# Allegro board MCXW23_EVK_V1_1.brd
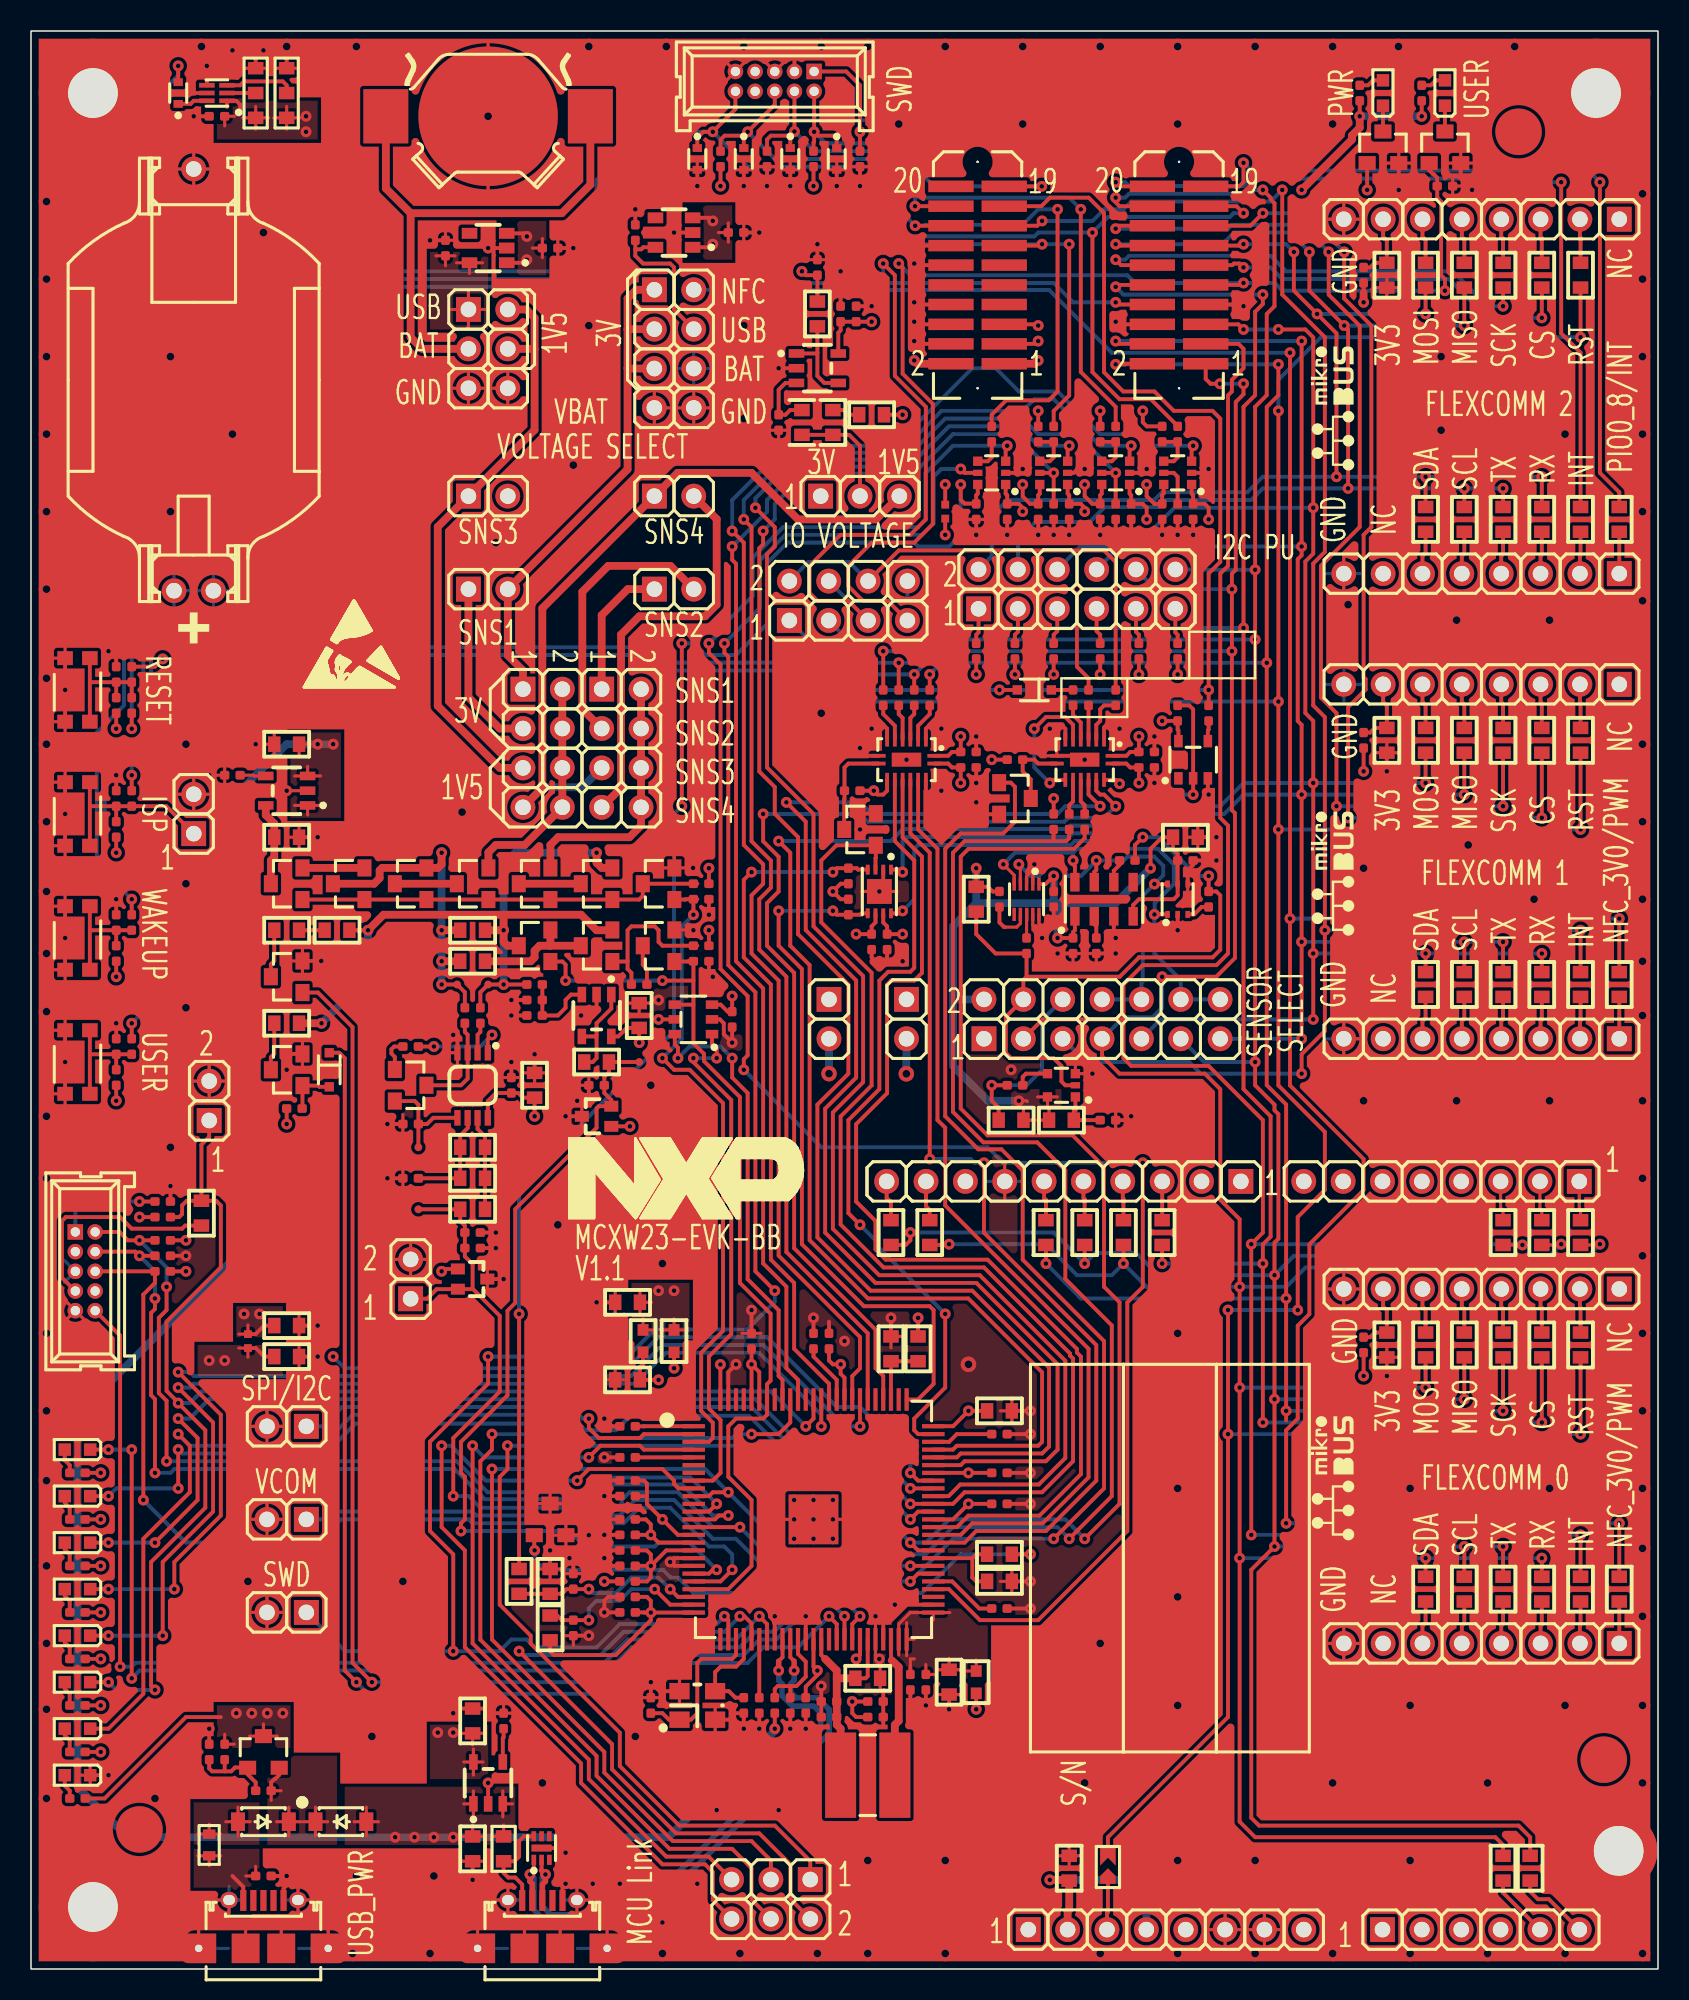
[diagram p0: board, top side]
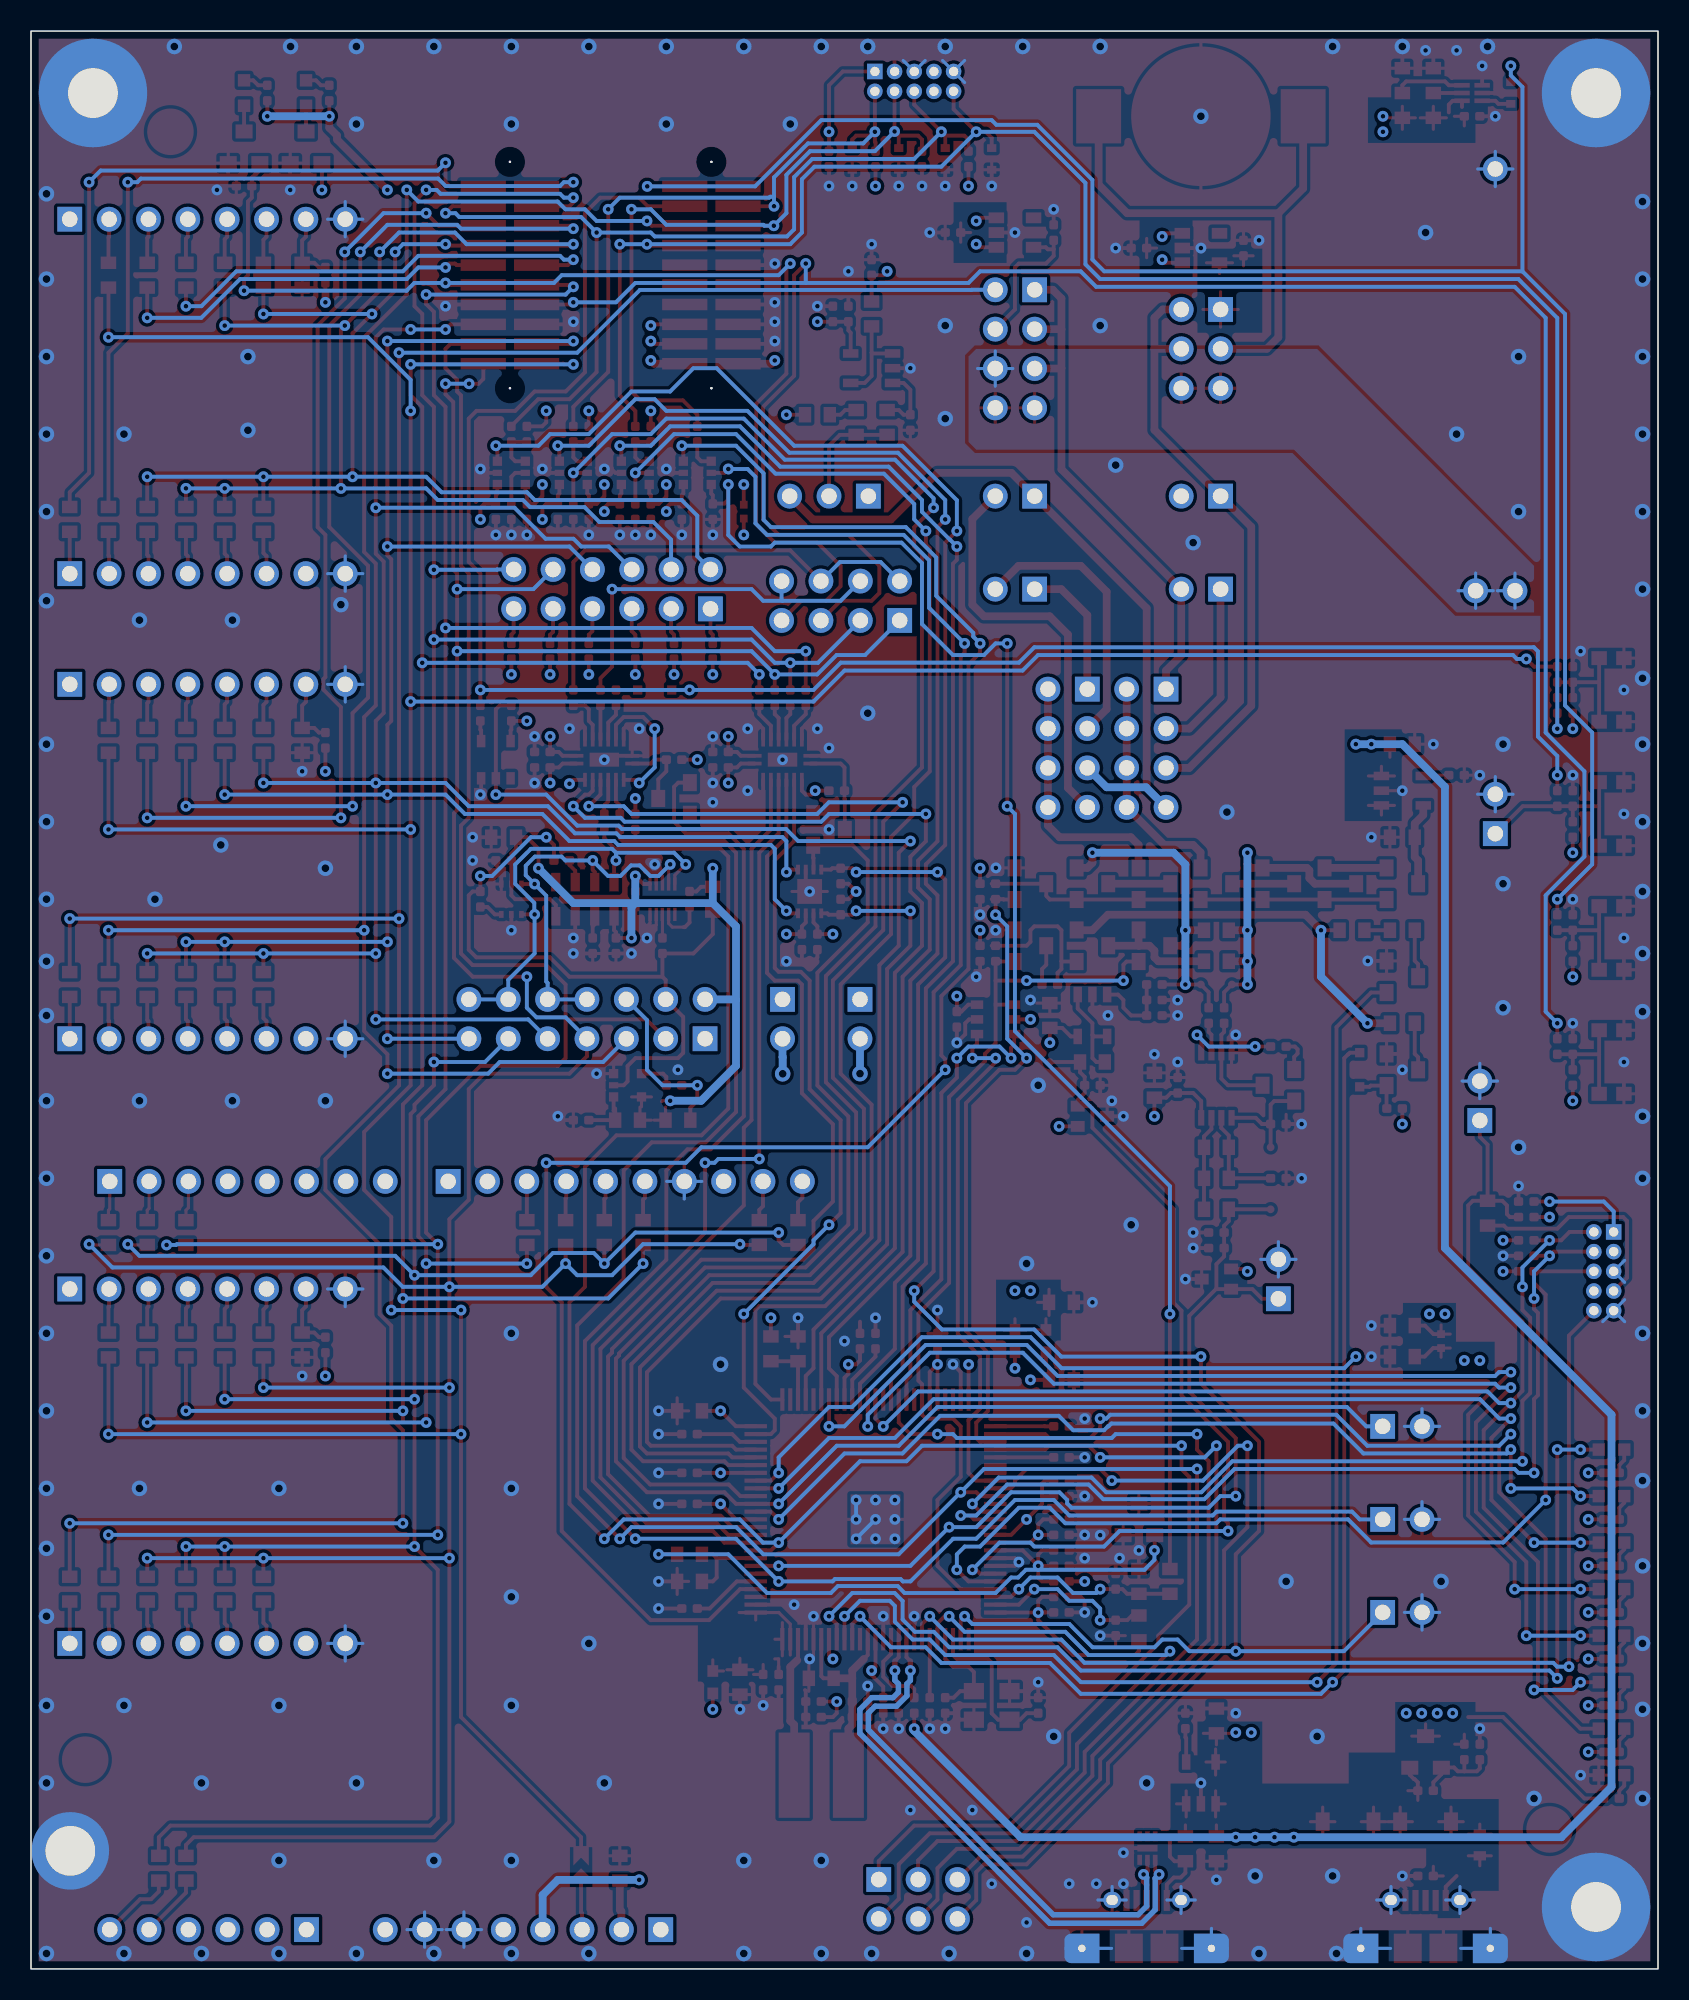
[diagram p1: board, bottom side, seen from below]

Outline 105 x 125 mm; copper layers: TOP, IN1, IN2, BOTTOM. Coordinates in mm from the lower left corner of the outline.
Outline path: rectangle 0,0 105,125

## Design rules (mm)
constraint set DEFAULT: 
net group USB: nets USB_DM USB_DP

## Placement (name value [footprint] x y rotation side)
BAT2  BATTERY_HOLDER  [RENATA-HU2032-LF]  10.5 102.5 90 top
BAT3  Keystone_3030  [KEYSTONE-3030]  29.5 119.5 0 top
BD1  470 Ohm @ 100MHz  [0603-R]  30.5 7.75 90 top
C1  1uF  [CC0402_25]  33.5 111 0 top
C2  1uF  [CC0402_25]  26.75 111 90 top
C3  100nF  [CC0402_25]  12 119.5 180 top
C4  1uF  [CC0402_25]  45.5 112 0 top
C5  1uF  [CC0402_25]  39 112 90 top
C6  100nF  [CC0402_25]  52.25 106.75 270 top
C7  1uF  [CC0402_25]  53.25 106.75 90 top
C8  10nF  [CC0402_25]  5.5 83.5 90 top
C9  10nF  [CC0402_25]  5.5 75.5 90 top
C10  10nF  [CC0402_25]  5.5 67.5 90 top
C11  10nF  [CC0402_25]  5.5 59.5 90 top
C12  100nF  [CC0402_25]  53.5 116.75 270 top
C13  100nF  [CC0402_25]  69.5 54.75 180 top
C14  100nF  [CC0402_25]  66 69 90 top
C15  100nF  [CC0402_25]  67.25 66 90 top
C16  100nF  [CC0402_25]  68.75 66 90 top
C17  100nF  [CC0402_25]  74.5 71.5 180 top
C18  10uF  [CC0603_OV]  87.5 40.25 270 top
C19  10uF  [CC0603_OV]  87.5 79.25 270 top
C20  10uF  [CC0603_OV]  87.5 109.25 270 top
C21  4.7UF  [CC0603_OV]  67 6.5 90 top
C22  100nF  [CC0402_25]  35 25 90 top
C23  100nF  [CC0402_25]  8.5 49.5 0 top
C24  10uF  [CC0603_OV]  62.5 36 0 top
C25  4.7UF  [CC0603_OV]  38.5 38 180 top
C26  100nF  [CC0402_25]  38.5 31.5 180 top
C27  100nF  [CC0402_25]  38.5 23 180 top
C28  100nF  [CC0402_25]  50 17 270 top
C29  100nF  [CC0402_25]  62.5 30 0 top
C30  100nF  [CC0402_25]  46.5 40.5 90 top
C31  10nF  [CC0402_25]  38.5 30.5 180 top
C32  10nF  [CC0402_25]  38.5 24 180 top
C33  10nF  [CC0402_25]  62.5 32 0 top
C34  10nF  [CC0402_25]  51.5 40.5 90 top
C35  47pF  [CC0402_25]  56.75 18.5 270 top
C36  100nF  [CC0402_25]  57.75 18.5 270 top
C37  22uF  [CC0603_OV]  59.25 18.5 270 top
C38  10uF  [CC0603_OV]  38.5 43 180 top
C39  100nF  [CC0402_25]  38.5 28 180 top
C40  47pF  [CC0402_25]  38.5 29 180 top
C41  47pF  [CC0402_25]  51.5 16.25 180 top
C42  100nF  [CC0402_25]  51.5 17.25 180 top
C43  22uF  [CC0603_OV]  54 18.75 0 top
C44  100nF  [CC0402_25]  38.5 27 180 top
C45  10nF  [CC0402_25]  38.5 26 180 top
C46  12PF  [CC0402_25]  46 17 270 top
C47  12PF  [CC0402_25]  40 17 90 top
C48  100nF  [CC0402_25]  54.5 17.25 0 top
C49  100nF  [CC0402_25]  54.5 16.25 0 top
C50  1uF  [CC0603_OV]  28.5 7.75 90 top
C51  4.7uF  [CC0603_OV]  28.5 16 90 top
C52  100nF  [CC0402_25]  30.5 16 90 top
C53  2.2UF  [CC0402_25]  15 6 0 top
C54  22uF  [CC0603_OV]  16.5 41.5 0 top
C55  22uF  [CC0603_OV]  16.5 39.5 0 top
C60  100nF  [CC0402_25]  45.25 61.25 270 top
C61  10uF  [CC0603_OV]  39.25 61.5 90 top
C62  1nF  [CC0402_25]  32.5 61.5 180 top
C63  10pF  [CC0402_25]  36.5 57 180 top
C64  10uF  [CC0603_OV]  32.5 57 90 top
C65  100nF  [CC0402_25]  31 57 90 top
C66  10pF  [CC0402_25]  28.5 46.5 0 top
C67  100PF  [CC0603_OV]  28.5 51 0 top
C68  100nF  [CC0402_25]  72 78.5 0 top
C69  100nF  [CC0402_25]  72 77.5 0 top
C70  100nF  [CC0402_25]  60.5 77.5 0 top
C71  100nF  [CC0402_25]  60.5 78.5 0 top
C72  100nF  [CC0402_25]  54.25 66.25 270 top
C73  100nF  [CC0402_25]  55.25 66.25 270 top
C74  100nF  [CC0402_25]  69 94 270 top
C75  100nF  [CC0402_25]  71 94 270 top
C76  100nF  [CC0402_25]  63 94 270 top
C77  100nF  [CC0402_25]  61 94 270 top
C78  100nF  [CC0402_25]  65 94 270 top
C79  100nF  [CC0402_25]  67 94 270 top
C80  100nF  [CC0402_25]  75 94 270 top
C81  100nF  [CC0402_25]  73 94 270 top
C83  100nF  [CC0402_25]  12.5 14 270 top
C87  4.7UF  [CC0603_OV]  74.5 73 0 top
C88  4.7uF  [CC0603_OV]  16.5 73 0 top
C89  100nF  [CC0402_25]  13 77 180 top
C90  1uF  [CC0603_OV]  16.5 79 0 top
D1  RB751S40T1G  [SOD523]  9.5 121 90 top
D2  GREEN  [KINGBRIGHT-KP1608]  91.25 121 270 top
D3  GREEN  [KINGBRIGHT-KP1608]  87.25 121 270 top
D4  PESD3V3S1UB  [SOD523]  43 116.75 270 top
D5  PESD3V3S1UB  [SOD523]  46 116.75 270 top
D6  PESD3V3S1UB  [SOD523]  49 116.75 270 top
D7  PESD3V3S1UB  [SOD523]  52 116.75 270 top
D8  GREEN  [KINGBRIGHT-KP1608]  3 27.5 0 top
D9  GREEN  [KINGBRIGHT-KP1608]  3 15.5 0 top
D10  RED  [KINGBRIGHT-KP1608]  3 18.5 0 top
D11  GREEN  [KINGBRIGHT-KP1608]  3 24.5 0 top
D12  GREEN  [KINGBRIGHT-KP1608]  3 21.5 0 top
D13  GREEN  [KINGBRIGHT-KP1608]  3 33.5 0 top
D14  GREEN  [KINGBRIGHT-KP1608]  3 30.5 0 top
D16  BLUE  [KINGBRIGHT-KP1608]  3 12.5 0 top
D17  PMEG6002EJ,115  [SOD323F-R]  64.75 82.5 180 top
D18  PMEG4010EGWX  [SOD123]  20 9.5 0 top
D19  PMEG4010EGWX  [SOD123]  15 9.5 180 top
D20  PMEG6002EJ,115  [SOD323F-R]  19.25 58 270 top
FIX1  3.2mm  [FM32_CU70]  4 4 0 top
FIX2  3.2mm  [FM32_CU70]  4 121 0 top
FIX3  3.2mm  [FM32_CU70]  101 121 0 top
FIX4  3.2mm  [FM32_CU70]  102.46 7.62 0 top
J1  CONN_HDR_4X2  [HE14-2X4PTS-MD]  33.02 78.74 270 top
J2  CONN_HDR_4X2  [HE14-2X4PTS-MD]  38.1 78.74 270 top
J3  CONN_HDR_3X1  [HE14-3PTS-MD]  53.5 95 0 top
J4  CONN_HDR_4X2  [HE14-2X4PTS-MD]  41.5 104.5 270 top
J5  CONN_HDR_3X2  [HE14-2X3PTS-MD]  29.5 104.5 270 top
J6  CONN_HDR_1X2  [HE14-2X1PTS-MD]  29.5 95 270 top
J7  CONN_HDR_1X2  [HE14-2X1PTS-MD]  41.5 95 270 top
J8  TFC-110-02-L-D-A  [SAMTEC-TFC-110-02-L-D-A]  61.09 109.26 0 top
J9  CONN_HDR_1X2  [HE14-2X1PTS-MD]  41.5 89 270 top
J10  CONN_HDR_1X2  [HE14-2X1PTS-MD]  29.5 89 270 top
J11  SHF-105-01-L-D-TH  [SAMTEC-SHF-105-01-L-D-TH]  48 121.75 180 top
J12  TFC-110-02-L-D-A  [SAMTEC-TFC-110-02-L-D-A]  74.09 109.26 0 top
J13  CONN_HDR_7X2  [HE14-2X7PTS-MD]  69.12 61.27 0 top
J14  CON SKT 8  [HE14-8PTS-MD]  93.61 43.86 180 top
J15  CON SKT 8  [HE14-8PTS-MD]  93.61 21 180 top
J16  CONN_HDR_2X1  [HE14-2X1PTS-MD]  56.5 61.27 180 top
J17  CON SKT 8  [HE14-8PTS-MD]  93.61 60 180 top
J18  CON SKT 8  [HE14-8PTS-MD]  93.61 82.86 180 top
J19  CONN_HDR_6X2  [HE14-2X6PTS-MD]  67.5 89 0 top
J20  CON SKT 8  [HE14-8PTS-MD]  93.61 112.86 180 top
J21  CON SKT 8  [HE14-8PTS-MD]  93.61 90 180 top
J22  CONN_HDR_2X1  [HE14-2X1PTS-MD]  51.5 61.27 180 top
J23  CON SKT 8  [HE14-8PTS-MD]  73.25 2.54 0 top
J24  Con_10x1  [HE14-10PTS-MD]  66.65 50.8 180 top
J25  Con_6x1  [HE14-6PTS-MD]  93.57 2.54 0 top
J26  CON SKT 8  [HE14-8PTS-MD]  91.03 50.8 180 top
J27  CONN_HDR_3X2  [HE14-2X3PTS-MD]  47.75 4.5 180 top
J28  CONN_HDR_2X1  [HE14-2X1PTS-MD]  16.5 35 90 top
J29  CONN_HDR_2X1  [HE14-2X1PTS-MD]  16.5 29 90 top
J30  CONN_HDR_2X1  [HE14-2X1PTS-MD]  16.5 23 90 top
J31  SHF-105-01-L-D-TH  [SAMTEC-SHF-105-01-L-D-TH]  3.5 45 270 top
J32  CONN_HDR_2X1  [HE14-2X1PTS-MD]  11.5 56 0 top
J33  USB Micro-B  [WE-629_105_150_921]  33 0 0 top
J34  USB Micro-B  [WE-629_105_150_921]  15 0 0 top
J35  CONN_HDR_2X1  [HE14-2X1PTS-MD]  24.5 44.5 0 top
J36  CONN_HDR_4X2  [HE14-2X4PTS-MD]  52.75 88.25 0 top
J37  CONN_HDR_2X1  [HE14-2X1PTS-MD]  10.5 74.5 0 top
JP37  Solderjumper  [PST-SD2]  69.5 6.5 0 top
L1  600OHM  [WE-CBF_0603-HS]  39.5 40.5 270 top
L2  600OHM  [WE-CBF_0603-HS]  61 18.5 90 top
L3  600OHM  [WE-CBF_0603-HS]  41.5 40.5 270 top
L4  4.7uH  [MURATA-LQH5BP]  54 12.5 180 top
L5  330 OHM  [TDK-MPZ1608]  11.5 8 90 top
L6  1K  [MURATA-BLM15]  14 40.5 270 top
L7  1K  [MURATA-BLM15]  59 94 270 top
NOREF  -  []  85 67 90 top
NOREF#2  -  []  -90 -64 0 top
NOREF#3  -  []  0 0 90 top
NOREF#4  -  [unnamed#2]  96 118.5 0 top
NOREF#5  -  []  -7 -7 0 top
NOREF#6  -  []  87 -10 0 top
NOREF#7  -  []  85 97 90 top
NOREF#8  -  []  105 0 90 top
NOREF#9  -  [unnamed#2]  7 9 0 top
NOREF#10  -  []  -7 132 0 top
NOREF#11  -  []  112 132 0 top
NOREF#12  -  []  85 28 90 top
NOREF#13  -  []  -87 -61 0 top
NOREF#14  -  []  0 125 0 top
NOREF#15  -  [unnamed#2]  101.5 13.5 0 top
NOREF#16  -  []  0 0 0 top
NOREF#17  -  []  202 -61 180 bottom
Q1  PMV30UN2R  [SOT23_GSD]  91.25 117.5 0 top
Q2  PMV30UN2R  [SOT23_GSD]  87.25 117.5 0 top
Q7  PMV30UN2R  [SOT23_GSD]  36.5 66 90 top
Q8  PMV30UN2R  [SOT23_GSD]  40.5 66 90 top
Q9  PMV30UN2R  [SOT23_GSD]  24.5 57 270 top
Q10  BSS138P  [SOT23_GSD]  63.5 75.5 270 top
Q11  BSS138P  [SOT23_GSD]  53.5 73.5 90 top
Q12  PMV65XP  [SOT23_GSD]  15 14 0 top
Q14  PMV27UPE  [SOT23_GSD]  32.5 66 90 top
Q16  PMV30UN2R  [SOT23_GSD]  16.5 58 90 top
Q17  PMV30UN2R  [SOT23_GSD]  16.5 64 90 top
Q20  Si2333DS  [SOT23_GSD]  16.5 70 90 top
Q21  PMV30UN2R  [SOT23_GSD]  40.5 70 90 top
Q22  Si2333DS  [SOT23_GSD]  20.5 70 90 top
Q24  PMV30UN2R  [SOT23_GSD]  28.5 70 90 top
Q25  PMV30UN2R  [SOT23_GSD]  24.5 70 90 top
Q26  PMV30UN2R  [SOT23_GSD]  32.5 70 90 top
Q27  PMV30UN2R  [SOT23_GSD]  36.5 70 90 top
R1  0R  [R603-X2]  14.5 121 90 top
R2  0R  [R603-X2]  16.5 121 90 top
R3  510  [RC0402_25]  89.75 121 90 top
R5  100K  [RC0402_25]  5.5 81.5 90 top
R6  100K  [RC0402_25]  5.5 73.5 90 top
R7  100K  [RC0402_25]  5.5 65.5 90 top
R8  100K  [RC0402_25]  5.5 57.5 90 top
R9  510  [RC0402_25]  85.75 121 90 top
R10  1K  [RC0402_25]  6.5 81.5 270 top
R11  1K  [RC0402_25]  6.5 83.5 90 top
R12  0R  [RC0603_OV]  51.75 99.75 90 top
R13  0R  [RC0603_OV]  54.25 100.25 0 top
R14  100K  [RC0402_25]  91.25 115 0 top
R15  1K  [RC0402_25]  6.5 75.5 90 top
R16  1K  [RC0402_25]  6.5 67.5 90 top
R17  0R  [RC0603_OV]  49.75 99.75 90 top
R18  100K  [RC0402_25]  50.75 109.75 90 top
R19  0R  [RC0603_OV]  50.75 106.75 90 top
R20  100K  [RC0402_25]  48.25 99.75 90 top
R21  1K  [RC0402_25]  6.5 59.5 90 top
R22  100K  [RC0402_25]  44.5 116.75 270 top
R23  100K  [RC0402_25]  50.5 116.75 270 top
R24  100K  [RC0402_25]  47.5 116.75 90 top
R25  10K  [RC0603_OV]  66.5 54.75 0 top
R26  10K  [RC0603_OV]  61 69 270 top
R27  1K  [RC0402_25]  63.5 57 0 top
R29  0R  [RC0402_25]  86 40.25 90 top
R30  0R  [RC0402_25]  86 79.25 90 top
R31  2.2K  [RC0402_25]  61 85 90 top
R32  2.2K  [RC0402_25]  66 85 90 top
R33  2.2K  [RC0402_25]  63.5 85 90 top
R34  2.2K  [RC0402_25]  71.5 85 90 top
R35  2.2K  [RC0402_25]  69 85 90 top
R36  2.2K  [RC0402_25]  74 85 90 top
R37  0R  [RC0402_25]  86 109.25 90 top
R38  200K  [RC0603_OV]  33.5 22 90 top
R39  100K  [RC0402_25]  35 22 270 top
R40  0  [RC0603_OV]  62.5 26.75 0 top
R41  0R  [RC0603_OV]  62.5 25 180 top
R42  2.0K  [RC0603_OV]  31.5 25 270 top
R43  2.0K  [RC0603_OV]  33.5 25 90 top
R44  510  [RC0402_25]  3 26 180 top
R45  510  [RC0402_25]  3 14 180 top
R46  1K  [RC0402_25]  62.5 23.25 0 top
R47  1K  [RC0402_25]  50.5 40.5 90 top
R48  1K  [RC0402_25]  62.5 34.5 0 top
R49  1K  [RC0402_25]  38.5 35 180 top
R50  1K  [RC0402_25]  47 17 270 top
R51  1K  [RC0402_25]  38.5 33 180 top
R52  100K  [RC0402_25]  8.5 45 180 top
R53  100K  [RC0402_25]  8.5 47 180 top
R54  510  [RC0402_25]  3 17 180 top
R55  100K  [RC0402_25]  8.5 48.5 0 top
R56  510  [RC0402_25]  3 23 180 top
R57  0  [RC0603_OV]  11 48.75 270 top
R58  510  [RC0402_25]  3 20 180 top
R59  510  [RC0402_25]  3 32 180 top
R60  100K  [RC0402_25]  8.5 46 0 top
R61  510  [RC0402_25]  3 29 180 top
R62  1K  [RC0402_25]  38.5 25 0 top
R63  10K  [RC0402_25]  48 17 90 top
R64  20K  [RC0402_25]  49 17 270 top
R65  510  [RC0402_25]  3 11 180 top
R66  10K  [RC0402_25]  43.25 70 0 top
R67  6.65K  [RC0603_OV]  16.5 61 0 top
R71  66.5  [RC0603_OV]  16.5 67 0 top
R72  330K  [RC0402_25]  43.25 66 0 top
R73  2  [RC0603_OV]  28.5 65 0 top
R74  10K  [RC0402_25]  43.25 65 0 top
R75  330K  [RC0402_25]  32.5 63.5 0 top
R76  0  [RC0603_OV]  36.5 58.5 0 top
R77  330K  [RC0402_25]  32.5 62.5 0 top
R78  100R  [RC0402_25]  29 61.5 270 top
R79  100R  [RC0402_25]  28 61.5 270 top
R80  49.9  [RC0402_25]  24.5 59.5 180 top
R81  1K  [RC0402_25]  24.5 51 0 top
R82  0  [RC0603_OV]  28.5 49 180 top
R83  1K  [RC0402_25]  24.5 54.5 180 top
R84  1K  [RC0402_25]  28.5 47.5 180 top
R85  2K  [RC0603_OV]  28.5 53 0 top
R87  100  [RC0402_25]  70 82 90 top
R88  10K  [RC0402_25]  66 74 270 top
R89  100  [RC0402_25]  68.25 82 90 top
R90  100  [RC0402_25]  67.25 82 90 top
R91  100  [RC0402_25]  68 74 90 top
R92  100  [RC0402_25]  67 74 90 top
R93  10K  [RC0402_25]  63.5 78 0 top
R94  100  [RC0402_25]  58 82 90 top
R95  100  [RC0402_25]  56 82 90 top
R96  100  [RC0402_25]  57 82 90 top
R97  100  [RC0402_25]  55 82 90 top
R98  10K  [RC0402_25]  53 76 180 top
R99  10K  [RC0402_25]  74 81 90 top
R100  10  [RC0402_25]  76 81 90 top
R101  2.2K  [RC0402_25]  52.75 68.5 270 top
R102  2.2K  [RC0402_25]  52.75 70.5 90 top
R104  100K  [RC0402_25]  69 99 270 top
R105  10  [RC0402_25]  70 99 90 top
R106  2.2K  [RC0402_25]  70 94 270 top
R108  100K  [RC0402_25]  65 99 270 top
R109  10  [RC0402_25]  62 99 90 top
R110  10  [RC0402_25]  66 99 90 top
R111  2.2K  [RC0402_25]  66 94 270 top
R112  100K  [RC0402_25]  73 99 270 top
R114  10  [RC0402_25]  74 99 90 top
R115  2.2K  [RC0402_25]  74 94 270 top
R116  0R  [RC0603_OV]  55.5 47.5 270 top
R118  0R  [RC0603_OV]  58 47.5 270 top
R119  0R  [RC0603_OV]  65.5 47.5 270 top
R120  0R  [RC0603_OV]  68 47.5 270 top
R121  0R  [RC0603_OV]  70.5 47.5 270 top
R122  0R  [RC0603_OV]  73 47.5 270 top
R123  0R  [RC0603_OV]  97.5 47.5 270 top
R124  0R  [RC0603_OV]  100 47.5 270 top
R125  0R  [RC0603_OV]  95 47.5 270 top
R126  0R  [RC0603_OV]  95 6.5 270 top
R127  0R  [RC0603_OV]  96.75 6.5 270 top
R128  0R  [RC0603_OV]  102.5 93.5 90 top
R129  0R  [RC0603_OV]  100 93.5 90 top
R130  0R  [RC0603_OV]  97.5 93.5 90 top
R131  0R  [RC0603_OV]  95 93.5 90 top
R132  0R  [RC0603_OV]  92.5 93.5 90 top
R133  0R  [RC0603_OV]  90 93.5 90 top
R134  0R  [RC0603_OV]  90 63.5 90 top
R135  0R  [RC0603_OV]  97.5 63.5 90 top
R136  0R  [RC0603_OV]  95 63.5 90 top
R137  0R  [RC0603_OV]  92.5 63.5 90 top
R138  0R  [RC0603_OV]  97.5 79.25 90 top
R139  0R  [RC0603_OV]  95 79.25 90 top
R140  0R  [RC0603_OV]  92.5 79.25 90 top
R141  0R  [RC0603_OV]  90 79.25 90 top
R142  0R  [RC0603_OV]  97.5 109.25 90 top
R143  0R  [RC0603_OV]  95 109.25 90 top
R144  0R  [RC0603_OV]  92.5 109.25 90 top
R145  0R  [RC0603_OV]  90 109.25 90 top
R146  0R  [RC0603_OV]  100 79.25 90 top
R147  0R  [RC0603_OV]  100 109.25 90 top
R148  0R  [RC0603_OV]  100 40.25 90 top
R149  0R  [RC0603_OV]  97.5 40.25 90 top
R150  0R  [RC0603_OV]  95 40.25 90 top
R151  0R  [RC0603_OV]  92.5 40.25 90 top
R152  0R  [RC0603_OV]  90 40.25 90 top
R153  0R  [RC0603_OV]  100 63.5 90 top
R154  0R  [RC0603_OV]  102.5 63.5 90 top
R155  0R  [RC0603_OV]  102.5 24.5 90 top
R156  0R  [RC0603_OV]  100 24.5 90 top
R157  0R  [RC0603_OV]  97.5 24.5 90 top
R158  0R  [RC0603_OV]  95 24.5 90 top
R159  0R  [RC0603_OV]  92.5 24.5 90 top
R160  0R  [RC0603_OV]  90 24.5 90 top
R161  10K  [RC0402_25]  15 11.5 180 top
R162  3k3  [RC0402_25]  11.5 14 90 top
R163  1K  [RC0402_25]  64.25 66 270 top
R164  1K  [RC0402_25]  70.75 71.5 0 top
R165  1K  [RC0402_25]  76 69 90 top
R166  1K  [RC0402_25]  62.5 69 90 top
R168  0R  [RC0603_OV]  55.5 40 270 top
R169  0R  [RC0603_OV]  57.25 40 270 top
R224  200  [RC0603_OV]  28.5 67 0 top
R227  10K  [RC0402_25]  43.25 69 180 top
R228  47K  [RC0402_25]  39.25 63.5 0 top
R229  10K  [RC0603_OV]  63.25 54.75 180 top
R230  1M  [RC0402_25]  17 55.5 0 top
R231  0.68  [RC0603_OV]  19.75 67 0 top
SW1  KMR221NG LFS  [CK-KMR2]  3 82.5 270 top
SW2  KMR221NG LFS  [CK-KMR2]  3 74.5 270 top
SW3  KMR221NG LFS  [CK-KMR2]  3 66.5 270 top
SW4  KMR221NG LFS  [CK-KMR2]  3 58.5 270 top
TP3  -  [TPAD_050]  39.25 58.5 270 top
TP4  -  [TPAD_050]  27.5 63.5 270 top
TP5  -  [TPAD_050]  29.5 63.5 270 top
TP6  -  [TPAD_050]  25 53 270 top
TP7  -  [TPAD_050]  25 49 270 top
U1  NCP115ASN150T2G  [TSOP-5]  29.5 111 270 top
U2  NMH1000  [VSON6]  12 121 180 top
U3  NCP699SN30T1G  [TSOP-5]  41.5 112 270 top
U4  MAX4165EUK+T  [SOT23-5-R]  50.75 103.25 90 top
U6  FXLS8974CF  [DFN10_DF]  64.25 69 270 top
U7  FXPQ3115BVT1  [LGA8-5X3]  69.25 69 90 top
U8  TMP117  [WSON6_DRV]  74 69 90 top
U9  LPC55S69JBD100  [HLQPF100-14X14]  50.5 29 270 top
U10  LM4040C30FTA  [SOT23-B-R]  33.5 29 0 top
U11  TC1017-3.3VCTTR  [SOT23-5-R]  29.5 12 180 top
U12  RClamp0854P.TCT  [SLP1616P6]  32.95 7.8 0 top
U16  74LVC1G175GV,125  [SOT457]  42.75 61.25 90 top
U17  LMV321RILT  [SOT23-5-R]  36.5 61.5 0 top
U18  BC857CW  [SC70-BEC]  36.5 55 90 top
U19  LTC2051IMS8  [MSOP8_MS]  28.5 57 180 top
U20  BC857CW  [SC70-BEC]  28.5 44.5 270 top
U21  74AVC4TD245BQ  [DHVQFN16]  68 78 180 top
U22  74AVC4TD245BQ  [DHVQFN16]  56.5 78 180 top
U23  74LVC1G07GV,125  [SOT753]  75 78 0 top
U24  PCA9617ATP  [HWSON8]  54.75 69.5 270 top
U25  74AUP1T45GW  [SOT363]  70 96.5 90 top
U26  74AUP1T45GW  [SOT363]  62 96.5 90 top
U27  74AUP1T45GW  [SOT363]  66 96.5 90 top
U28  74AUP1T45GW  [SOT363]  74 96.5 90 top
U29  74AUP1G09GW  [SOT353]  66.5 57 90 top
U30  TC1017-3.3VCTTR  [SOT23-5-R]  16.5 76 270 top
Y1  16MHz  [CX3225CA]  43 17 0 top

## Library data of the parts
BAT2 = BATTERY_HOLDER_0
BAT3 = Keystone_3030
BD1 = INDUCTOR_0
C1 C2 C4 C5 C7 C13-C17 C51 C52 C88 C89 = CAPACITOR _0
C3 C6 C8-C12 C18-C49 C53-C55 C60-C81 C83 C87 = CAP_NP
C50 C90 = CAP NP
D1 D17 D20 = DIODE_SCHTKY
D2 D3 D8-D14 D16 = LED
D4-D7 = DIODE_TVS
D18 = DIODE SCHOTTKY_2
D19 = DIODE SCHOTTKY_3
FIX1-FIX4 = FIX
J1 J2 J4 J36 = CONN_HDR_4X2
J3 = CONN_HDR_3X1
J5 J27 = CONN_HDR_3X2
J6 J7 J9 J10 = CONN_HDR_1X2
J8 J12 = HEADER 10X2
J11 J31 = CONN_HDR_5X2
J13 = CONN_HDR_7X2
J14 J15 J17 J18 J20 J21 J23 J26 = CONN_HDR_8X1
J16 J22 J28-J30 J32 J35 J37 = CONN_HDR_2X1
J19 = CONN_HDR_6X2
J24 = Con_10x1
J25 = Con_6x1
J33 J34 = USB_MINI_B_SKT_3
JP37 = Solderjumper
L1-L4 = INDUCTOR
L5-L7 = BEAD
Q1 Q2 Q7-Q11 Q16 Q17 Q21 Q24-Q27 = MOSFET_N_0
Q12 Q14 Q20 Q22 = MOSFET_P_0
R1 R2 = RES_3PIN
R3 R5-R27 R29-R67 R71-R85 R87 R89-R92 R94-R97 R99-R102 R104-R106 R108-R112 R114-R116 R118-R166 R168 R169 R224 R227-R231 = RES
R88 R93 R98 = RES: tolerance: 5%
SW1-SW4 = SW_PB_0
TP3-TP7 = TEST POINT L
U1 U3 U11 U30 = TPS76930_1
U2 = NMH1000
U4 U17 = OPAMP_SGL_5P
U6 = FXLS8974CF
U7 = FXPQ3115BV
U8 = TMP117_0
U9 = LPC55S69JB_HLQFP100
U10 = LM4040_SOT23_0
U12 = RCLAMP1654P_NEW
U16 = 1_D_FLIPFLOP_6P
U18 U20 = PNP_0
U19 = OPAMP_DUAL_8P_B
U21 U22 = 74AVC4TD245BQ_DHVQFN16_1
U23 = 74AUP1G07GW
U24 = PCA9617ATP
U25-U28 = 74LVCH1T45_6P
U29 = 74AUP1G09GW,125
Y1 = XTAL_0

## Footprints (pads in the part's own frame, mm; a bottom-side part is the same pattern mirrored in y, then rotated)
0603-R
  rect 0.8x1 smd: 1(-0.8,0) 2(0.8,0)
CC0402_25
  custom 0.14x0.14 smd: 1(-0.5,0) 2(0.5,0)
CC0603_OV
  rect 0.8x1 smd: 1(-0.8,0) 2(0.8,0)
CK-KMR2
  rect 0.9x1 smd: 1(2.05,0.8) 2(2.05,-0.8) 3(-2.05,0.8) 4(-2.05,-0.8)
CX3225CA
  rect 1.3x1.05 smd: 1(-1.15,-0.92) 2(1.15,-0.92) 3(1.15,0.92) 4(-1.15,0.92)
DFN10_DF
  rect 0.85x0.22 smd: 1(-0.98,0.8) 2(-0.98,0.4) 3(-0.98,0) 4(-0.98,-0.4) 5(-0.98,-0.8) 6(0.98,-0.8) 7(0.98,-0.4) 8(0.98,0.01) 9(0.98,0.4) 10(0.98,0.8)
DHVQFN16
  rect 0.9x0.24 smd: 1(-1.8,-0.25) 8(1.8,-0.25) 9(1.8,0.25) 16(-1.8,0.25)
  rect 0.24x0.9 smd: 2(-1.25,-1.3) 3(-0.75,-1.3) 4(-0.25,-1.3) 5(0.25,-1.3) 6(0.75,-1.3) 7(1.25,-1.3) 10(1.25,1.3) 11(0.75,1.3) 12(0.25,1.3) 13(-0.25,1.3) 14(-0.75,1.3) 15(-1.25,1.3)
  rect 1.9x0.9 smd: PAD(0,0)
FM32_CU70
  round 7 hole 3.2: 1(0,0)
HE14-2X1PTS-MD
  rect 1.6x1.6 hole 1: 1(0,-1.27)
  round 1.6 hole 1: 2(0,1.27)
HE14-2X3PTS-MD
  rect 1.6x1.6 hole 1: 1(-2.54,-1.27)
  round 1.6 hole 1: 2(-2.54,1.27) 3(0,-1.27) 4(0,1.27) 5(2.54,-1.27) 6(2.54,1.27)
HE14-2X4PTS-MD
  rect 1.6x1.6 hole 1: 1(-3.81,-1.27)
  round 1.6 hole 1: 2(-3.81,1.27) 3(-1.27,-1.27) 4(-1.27,1.27) 5(1.27,-1.27) 6(1.27,1.27) 7(3.81,-1.27) 8(3.81,1.27)
HE14-2X6PTS-MD
  rect 1.6x1.6 hole 1: 1(-6.35,-1.27)
  round 1.6 hole 1: 2(-6.35,1.27) 3(-3.81,-1.27) 4(-3.81,1.27) 5(-1.27,-1.27) 6(-1.27,1.27) 7(1.27,-1.27) 8(1.27,1.27) 9(3.81,-1.27) 10(3.81,1.27) 11(6.35,-1.27) 12(6.35,1.27)
HE14-2X7PTS-MD
  rect 1.6x1.6 hole 1: 1(-7.62,-1.27)
  round 1.6 hole 1: 2(-7.62,1.27) 3(-5.08,-1.27) 4(-5.08,1.27) 5(-2.54,-1.27) 6(-2.54,1.27) 7(0,-1.27) 8(0,1.27) 9(2.54,-1.27) 10(2.54,1.27) 11(5.08,-1.27) 12(5.08,1.27) 13(7.62,-1.27) 14(7.62,1.27)
HE14-3PTS-MD
  rect 1.6x1.6 hole 1: 1(-2.54,0)
  round 1.6 hole 1: 2(0,0) 3(2.54,0)
HE14-6PTS-MD
  rect 1.6x1.6 hole 1: 1(-6.35,0)
  round 1.6 hole 1: 2(-3.81,0) 3(-1.27,0) 4(1.27,0) 5(3.81,0) 6(6.35,0)
HE14-8PTS-MD
  rect 1.6x1.6 hole 1: 1(-8.89,0)
  round 1.6 hole 1: 2(-6.35,0) 3(-3.81,0) 4(-1.27,0) 5(1.27,0) 6(3.81,0) 7(6.35,0) 8(8.89,0)
HE14-10PTS-MD
  rect 1.6x1.6 hole 1: 1(-11.43,0)
  round 1.6 hole 1: 2(-8.89,0) 3(-6.35,0) 4(-3.81,0) 5(-1.27,0) 6(1.27,0) 7(3.81,0) 8(6.35,0) 9(8.89,0) 10(11.43,0)
HLQPF100-14X14
  rect 0.27x1.45 smd: 1(-6.01,-7.73) 2(-5.5,-7.73) 3(-5,-7.73) 4(-4.5,-7.73) 5(-4,-7.73) 6(-3.5,-7.73) 7(-3,-7.73) 8(-2.5,-7.73) 9(-2,-7.73) 10(-1.5,-7.73) 11(-1,-7.73) 12(-0.5,-7.73) 13(0,-7.73) 14(0.5,-7.73) 15(1,-7.73) 16(1.5,-7.73) 17(2,-7.73) 18(2.5,-7.73) 19(3,-7.73) 20(3.5,-7.73) 21(4,-7.73) 22(4.5,-7.73) 23(5,-7.73) 24(5.5,-7.73) 25(6.01,-7.73) 51(6.01,7.73) 52(5.5,7.73) 53(5,7.73) 54(4.5,7.73) 55(4,7.73) 56(3.5,7.73) 57(3,7.73) 58(2.5,7.73) 59(2,7.73) 60(1.5,7.73) 61(1,7.73) 62(0.5,7.73) 63(0,7.73) 64(-0.5,7.73) 65(-1,7.73) 66(-1.5,7.73) 67(-2,7.73) 68(-2.5,7.73) 69(-3,7.73) 70(-3.5,7.73) 71(-4,7.73) 72(-4.5,7.73) 73(-5,7.73) 74(-5.5,7.73) 75(-6.01,7.73)
  rect 1.45x0.27 smd: 26(7.73,-6.01) 27(7.73,-5.5) 28(7.73,-5) 29(7.73,-4.5) 30(7.73,-4) 31(7.73,-3.5) 32(7.73,-3) 33(7.73,-2.5) 34(7.73,-2) 35(7.73,-1.5) 36(7.73,-1) 37(7.73,-0.5) 38(7.73,0) 39(7.73,0.5) 40(7.73,1) 41(7.73,1.5) 42(7.73,2) 43(7.73,2.5) 44(7.73,3) 45(7.73,3.5) 46(7.73,4) 47(7.73,4.5) 48(7.73,5) 49(7.73,5.5) 50(7.73,6.01) 76(-7.73,6.01) 77(-7.73,5.5) 78(-7.73,5) 79(-7.73,4.5) 80(-7.73,4) 81(-7.73,3.5) 82(-7.73,3) 83(-7.73,2.5) 84(-7.73,2) 85(-7.73,1.5) 86(-7.73,1) 87(-7.73,0.5) 88(-7.73,0) 89(-7.73,-0.5) 90(-7.73,-1) 91(-7.73,-1.5) 92(-7.73,-2) 93(-7.73,-2.5) 94(-7.73,-3) 95(-7.73,-3.5) 96(-7.73,-4) 97(-7.73,-4.5) 98(-7.73,-5) 99(-7.73,-5.5) 100(-7.73,-6.01)
  rect 3.21x3.21 smd: 101(0,0)
HWSON8
  rect 0.63x0.25 smd: 1(-1.41,0.75) 2(-1.41,0.25) 3(-1.41,-0.25) 4(-1.41,-0.75) 5(1.41,-0.75) 6(1.41,-0.25) 7(1.41,0.25) 8(1.41,0.75)
  rect 1.6x1.6 smd: 9(0,0)
KEYSTONE-3030
  rect 2.9x3.5 smd: 1(-6.6,0) 3(6.6,0)
  round 9 smd: 2(0,0)
KINGBRIGHT-KP1608
  rect 0.8x0.8 smd: A(-0.82,0) C(0.82,0)
LGA8-5X3
  rect 1.2x0.6 smd: 1(-1.1,1.88) 2(-1.1,0.63) 3(-1.1,-0.63) 4(-1.1,-1.88) 5(1.1,-1.88) 6(1.1,-0.63) 7(1.1,0.63) 8(1.1,1.88)
MSOP8_MS
  rect 0.4x1 smd: 1(-0.98,-2.1) 2(-0.32,-2.1) 3(0.32,-2.1) 4(0.98,-2.1) 5(0.98,2.1) 6(0.32,2.1) 7(-0.32,2.1) 8(-0.98,2.1)
MURATA-BLM15
  rect 0.5x0.5 smd: 1(-0.45,0) 2(0.45,0)
MURATA-LQH5BP
  rect 2x5.5 smd: 1(-1.75,0) 2(1.75,0)
PST-SD2
  custom 0.25x0.25 smd: 1(0,0.8) 2(0,-0.5)
R603-X2
  rect 0.8x1 smd: 1(-1.6,0) 2(0,0) 3(1.6,0)
RC0402_25
  custom 0.14x0.14 smd: 1(-0.5,0) 2(0.5,0)
RC0603_OV
  rect 0.8x1 smd: 1(-0.8,0) 2(0.8,0)
RENATA-HU2032-LF
  round 1.6 hole 1: 1(13.6,0) 2(-13.6,1.27) 3(-13.6,-1.27)
SAMTEC-SHF-105-01-L-D-TH
  rect 1x1 hole 0.6: 1(-2.54,-0.64)
  round 1 hole 0.6: 2(-2.54,0.64) 3(-1.27,-0.64) 4(-1.27,0.64) 5(0,-0.64) 6(0,0.64) 7(1.27,-0.64) 8(1.27,0.64) 9(2.54,-0.64) 10(2.54,0.64)
SAMTEC-TFC-110-02-L-D-A
  round 0.15 hole 1.5 unplated: (0,7.3) (0,-7.3)
  rect 2.92x0.74 smd: 1(1.72,-5.72) 2(-1.72,-5.72) 3(1.72,-4.44) 4(-1.72,-4.44) 5(1.72,-3.18) 6(-1.72,-3.18) 7(1.72,-1.9) 8(-1.72,-1.9) 9(1.72,-0.64) 10(-1.72,-0.64) 11(1.72,0.64) 12(-1.72,0.64) 13(1.72,1.9) 14(-1.72,1.9) 15(1.72,3.18) 16(-1.72,3.18) 17(1.72,4.44) 18(-1.72,4.44) 19(1.72,5.72) 20(-1.72,5.72)
SC70-BEC
  rect 0.7x0.9 smd: B(-0.65,-0.95) C(0,0.95) E(0.65,-0.95)
SLP1616P6
  rect 0.3x0.65 smd: 1(-0.5,-0.76) 2(0,-0.76) 3(0.5,-0.76) 4(0.5,0.76) 5(0,0.76) 6(-0.5,0.76)
  rect 1.3x0.45 smd: 7(0,0)
SOD123
  rect 0.9x1.2 smd: A(1.64,0) C(-1.64,0)
SOD323F-R
  rect 0.6x0.6 smd: A(1.1,0) C(-1.1,0)
SOD523
  rect 0.5x0.6 smd: A(0.7,0) C(-0.7,0)
SOT23-5-R
  rect 0.55x1 smd: 1(0.95,1.35) 2(0,1.35) 3(-0.95,1.35) 4(-0.95,-1.35) 5(0.95,-1.35)
SOT23-B-R
  rect 1.1x0.9 smd: A(1.02,-1.02) C(-1.02,-1.02) NC(0,1.02)
SOT23_GSD
  rect 1.1x0.9 smd: D(0,1.02) G(-1.02,-1.02) S(1.02,-1.02)
SOT353
  rect 0.6x0.6 smd: 1(-0.75,-0.9) 3(0.75,-0.9) 4(0.75,0.9) 5(-0.75,0.9)
  rect 0.4x0.6 smd: 2(0,-0.9)
SOT363
  rect 0.6x0.6 smd: 1(-0.75,-0.9) 3(0.75,-0.9) 4(0.75,0.9) 6(-0.75,0.9)
  rect 0.4x0.6 smd: 2(0,-0.9) 5(0,0.9)
SOT457
  rect 0.55x0.8 smd: 1(-0.95,-1.2) 2(0,-1.2) 3(0.95,-1.2) 4(0.95,1.2) 5(0,1.2) 6(-0.95,1.2)
SOT753
  rect 0.55x0.8 smd: 1(-0.95,-1.2) 2(0,-1.2) 3(0.95,-1.2) 4(0.95,1.2) 5(-0.95,1.2)
TDK-MPZ1608
  rect 0.6x0.8 smd: 1(-0.7,0) 2(0.7,0)
TPAD_050
  round 0.5 smd: 1(0,0)
TSOP-5
  rect 0.7x1 smd: 1(0.95,1.2) 2(0,1.2) 3(-0.95,1.2) 4(-0.95,-1.2) 5(0.95,-1.2)
unnamed#2
  round 1.5 smd: (0,0)
VSON6
  rect 1x0.3 smd: 1(-0.65,0.5) 2(-0.65,0) 3(-0.65,-0.5) 4(0.65,-0.5) 5(0.65,0) 6(0.65,0.5)
WE-629_105_150_921
  rect 0.4x1.35 smd: 1(-1.3,4.42) 2(-0.65,4.42) 3(0,4.42) 4(0.65,4.42) 5(1.3,4.42)
  oval 1.1x1.05 hole 0.75x0.65: F1(-2.22,4.45) F2(2.23,4.45)
  custom 0.475x0.475 hole 1.3x0.8: F3(-4.18,1.33) F6(4.18,1.33)
  rect 1.8x1.9 smd: F4(-1.15,1.33) F5(1.15,1.33)
WE-CBF_0603-HS
  rect 0.75x0.7 smd: 1(-0.72,0) 2(0.72,0)
WSON6_DRV
  rect 0.45x0.3 smd: 1(-0.98,0.65) 2(-0.98,0) 3(-0.98,-0.65) 4(0.98,-0.65) 5(0.98,0) 6(0.98,0.65)

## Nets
1V5: J1.7 J2.5 J3.3 J6.2 J7.1
1V5_SNS+: J1.5 J5.2 J5.4 J6.1
1V5_SNS-: J2.7 J7.2 J8.1
3V0: J1.3 J2.1 J3.1 J9.1 J10.1 R3.1 R9.1
3V0_SNS+: J1.1 J4.1 J4.3 J4.5 J10.2
3V0_SNS-: J2.3 J8.2 J9.2
3V3: C23.1 C38.1 C51.1 C60.1 C69.1 C70.1 C72.1 C75.1 C76.1 C79.1 C80.1 J31.1 L1.1 L2.1 L3.1 R44.1 R45.1 R52.1 R53.1 R54.1 R55.1 R56.1 R58.1 R59.1 R61.1 R88.1 R101.1 R102.1 R169.1 R230.1 U11.5(OUT) U16.3 U16.5(VCC) U18.B U20.B U21.16(VCCB) U22.16(VCCB) U24.6(VCCB) U25.1 U26.1 U27.1 U28.1
+3V3_1V8_ARD: C21.1 J22.2 J23.2 J23.4 J24.8
GND: BAT2.1 BAT3.2(-) C1.2 C2.2 C3.2 C4.2 C5.2 C6.1 C7.2 C8.2 C9.2 C10.2 C11.2 C12.2 C13.1 C14.1 C15.1 C16.1 C17.1 C18.2 C19.2 C20.2 C21.2 C22.2 C23.2 C24.2 C25.2 C26.2 C27.2 C28.2 C29.2 C30.2 C31.2 C32.2 C33.2 C34.2 C35.2 C36.2 C37.2 C38.2 C39.2 C40.2 C41.2 C42.2 C43.2 C44.2 C45.2 C46.2 C47.2 C48.2 C49.2 C50.1 C51.2 C52.2 C53.2 C54.2 C55.2 C60.2 C61.2 C62.2 C63.2 C64.2 C65.2 C66.2 C68.2 C69.2 C70.2 C71.2 C72.2 C73.2 C74.2 C75.2 C76.2 C77.2 C78.2 C79.2 C80.2 C81.2 C87.2 C88.2 C89.2 C90.1 D4.A D5.A D6.A D7.A D16.C(CATHODE) FIX1.1 FIX2.1 FIX3.1 FIX4.1 J4.7 J4.8(B4) J5.5 J5.6(B3) J8.4 J8.6 J8.8 J8.12 J8.14 J11.3 J11.5 J11.9 J12.6 J12.7 J14.8 J15.8 J17.8 J18.8 J20.8 J21.8 J23.6 J23.7 J24.7 J28.2 J29.2 J30.2 J31.3 J31.5 J31.9 J32.2 J33.5 J33.F1 J33.F2 J33.F3 J33.F4 J33.F5 J33.F6 J34.5 J34.F1 J34.F2 J34.F3 J34.F4 J34.F5 J34.F6 J35.2 J37.2 Q1.S(SOURCE) Q2.S(SOURCE) Q8.S(SOURCE) Q10.S(SOURCE) Q11.S(SOURCE) Q16.S(SOURCE) Q17.S(SOURCE) Q21.S(SOURCE) R1.3 R2.3 R14.2 R18.2 R20.1 R24.1 R39.2 R41.1 R43.2 R46.2 R47.2 R48.2 R49.2 R50.2 R51.2 R60.2 R64.2 R74.2 R77.1 R81.1 R83.2 R84.1 R106.2 R111.2 R115.2 R162.2 R168.1 R227.1 SW1.2 SW1.4 SW2.2 SW2.4 SW3.2 SW3.4 SW4.2 SW4.4 U1.2 U2.4 U2.5 U3.2 U4.2(VSS) U6.2 U6.3 U6.9 U6.10 U7.3 U8.2 U8.4 U9.18 U9.19 U9.33 U9.37 U9.46 U9.47 U9.52 U9.99 U9.101 U10.A U10.NC U11.2 U12.7 U16.2 U17.2(VSS) U18.C U19.4 U20.C U21.2 U21.7 U21.8 U21.PAD U22.2 U22.7 U22.8 U22.15 U22.PAD U23.3 U24.2 U24.9 U25.2 U26.2 U27.2 U28.2 U29.3 U30.2 Y1.2 Y1.4
P5VA: C54.1 C61.1 C64.1 C65.1 L6.1 R66.2 R72.2 U17.5 U19.8
VBAT_DCDC/VBAT_PMU: C35.1 C36.1 C37.1 L2.2 U9.49 U9.50 U9.51
VBUS: BD1.2 C50.2 C90.2 D18.A R63.1 U11.1 U11.3 U30.1 U30.3
VCC_IF_LINK: C74.1 C77.1 C78.1 C81.1 L7.1 R42.1 R104.1 R108.1 R112.1 U25.6(VCCB) U26.6(VCCB) U27.6(VCCB) U28.6(VCCB)
VCC_MIKROE: J16.2 R29.1 R30.1 R37.1
ADC0_CH1_CURR: C66.1 J35.1 R82.2 R84.2 TP7.1(TP) U9.14 U9.57 U20.E
ADC1_CH1_V: C63.1 R76.2 TP3.1(TP) U9.20 U18.E
ARD_D2: J26.3 R125.1
ARD_D18: J25.5 R126.2
ARD_D19: J25.6 R127.2
ARD_IIC_SCK: J24.10 R116.1
ARD_IIC_SDA: J24.9 R118.1
ARD_RXD: J26.1 R124.1
ARD_SPI_LIFO: J24.5 R120.1
ARD_SPI_LOFI: J24.4 R121.1
ARD_SPI_SCK: J24.6 R119.1
ARD_SPI_SS: J24.3 R122.1
ARD_TXD: J26.2 R123.1
BRG_I2C0_SCL: R101.2 U9.76 U24.5
BRG_I2C0_SDA: R102.2 U9.86 U24.4
BRG_SPI1_MISO: U9.62 U22.12
BRG_SPI1_MOSI: U9.60 U22.13
BRG_SPI1_SCLK: U9.61 U22.14
BRG_SPI1_SSEL: U9.74 U22.11
CTRL_CAL_DISC: Q21.G R227.2 U9.3
CTRL_CAL_R1: D20.C U9.41
CTRL_CAL_R2: Q17.G U9.42
CTRL_HIGH_CURR: Q8.G Q14.G R74.1 U9.22 U9.94 U16.4
CTRL_HIGH_CURR_DIS: U9.92 U16.6
CTRL_HIGH_CURR_EN: U9.8 U16.1
CURR_RANGE_SET: R38.2 R39.1 U9.24
CURR_SNS+: J1.2 J1.4 J1.6 J1.8(B4) Q24.S(SOURCE)
CURR_SNS-: J2.2 J2.4 J2.6 J2.8(B4) Q26.S(SOURCE)
DBGIF_DETECT: R168.2 R169.2 U9.78
DBGIF_ISP0_CTRL: R99.2 U9.72 U23.2
DBGIF_RESET: U9.90 U27.3
DBGIF_RESET_TXEN: R111.1 U9.71 U27.5
DBGIF_TCK_SWCLK: U9.54 U26.3
DBGIF_TDO_SWO: U9.83 U28.3
DBGIF_TMS_SWDIO: U9.81 U25.3
DBGIF_TMS_SWDIO_TXEN: R106.1 U9.66 U25.5
DBGIF_VREF: C22.1 R42.2 R43.1 U9.23
FUNC: D12.C(CATHODE) U9.87
HW_VER_0: R47.1 U9.85
HW_VER_1: R48.1 U9.73
HW_VER_2: J28.1 Q11.G U9.65 U24.3
HW_VER_3: R49.1 U9.1
HW_VER_4: R50.1 U9.31
HW_VER_5: R51.1 U9.5
HW_VER_6: J29.1 Q10.G U9.56
HW_VER_7: J30.1 U9.27 U26.5
HW_VER_8: R46.1 U9.55
LED_NRG: D14.C(CATHODE) U9.64
LED_SIO: D13.C(CATHODE) U9.43
LED_SWO_ACT: D9.C(CATHODE) U9.2
LED_USB_COMM: D8.C(CATHODE) U9.67
LED_VCOM_ACT: D11.C(CATHODE) U9.82
LPC_P1_7-MCULINK: J27.6(B3) U9.9
LPC_P1_20-MCULINK: J27.5 U9.4
LPC_P1_21-MCULINK: J27.2 U9.30
LPC_P1_31-MCULINK: J27.4 U9.91
LPC_PIO0_5-ISP_EN-LED_SWD_ACT: D10.C(CATHODE) J32.1 R55.2 R57.1 U9.88
LPC_PIO0_10-SWO: J31.6 R52.2 U9.21
LPC_PIO0_11-SWDCLK: J31.4 R60.1 U9.13
LPC_PIO0_12-SWDIO: J31.2 R53.2 U9.12
MCU_LINK_3V3: C24.1 C25.1 C26.1 C27.1 C28.1 C29.1 C30.1 C31.1 C32.1 C33.1 C34.1 C48.1 C49.1 L1.2 R38.1 U9.15 U9.25 U9.38 U9.44 U9.63 U9.69 U9.75 U9.84 U9.95 U9.96 U9.100
MCU_LINK_N_16MHZ: C47.1 U9.28 Y1.1
MCU_LINK_P_16MHZ: C46.1 U9.29 Y1.3
MCU_LINK_RST: J31.10(B5) U9.32
MCU_LNK_RX: U9.70 U21.13
MCU_LNK_TX: U9.79 U21.14
MCULINK_VDDA: C39.1 C40.1 L3.2 R62.1 U9.16
NFC_3V0: J4.2 R154.2 R155.2
P1_1-MCULINK: J27.1 R91.1 U9.59
P1_9-MCULINK: J27.3 R88.2 R92.1 U9.10(PIO1_9/ADC0_12)
PIO0_0-FC0_CTS_SDA_SSEL0: J12.10 R97.2 R122.2 R149.1
PIO0_1: J12.3 J13.3 R125.2 R156.2
PIO0_2-FC0_RXD_SDA_MOSI: J12.1 J13.7 J19.10 J36.1 R96.2 R118.2 R121.2 R124.2 R126.1 R152.1 R157.2 R160.2
PIO0_3-FC0_TXD_SCL_MISO: J12.18 J13.11 J19.12(B6) J36.3 R95.2 R116.2 R120.2 R123.2 R127.1 R151.1 R158.2 R159.2
PIO0_4-FC0_SCK: J12.2 R94.2 R119.2 R150.1
PIO0_5-FC2_CTS_SDA_SSEL0: J12.11 R142.1
PIO0_6-FC2_RXD_SDA_MOSI-SPIFI_IO0: J12.13 J19.2 R130.2 R133.2 R145.1
PIO0_7-FC2_TXD_SCL_MISO-SPIFI_IO1: J12.14 J19.4 R131.2 R132.2 R144.1
PIO0_8-SPIFI_IO2: J12.19 R128.2
PIO0_9-SPIFI_IO3: J12.20 R129.2
PIO0_10-FC2_SCK: J12.12 R143.1
PIO0_11-SWDCLK: D6.C J8.16 J11.4 R24.2 R109.2
PIO0_12-SWDIO: D7.C J8.18 J11.2 R23.1 R105.2
PIO0_13-FC1_RXD_SDA_MOSI: J12.5 J13.9 J19.6 R134.2 R135.2 R141.1 U24.1
PIO0_14-FC1_TXD_SCL_MISO: J12.4 J13.13 J19.8 R136.2 R137.2 R140.1 U24.8
PIO0_15-FC1_CTS_SDA_SSEL0: J12.15 R138.1
PIO0_16-FC1_SCK: J12.16 R139.1
PIO0_17-SWO: D5.C J11.6 J12.17 R22.1 R114.2
PIO0_18-FC2_RXD_SDA_MOSI: J12.8 J36.5 R21.2
PIO0_19-FC2_TXD_SCL_MISO: J12.9 J36.7 Q1.G R14.1
PIO0_20-ISP: D17.A J8.17 R15.2 R100.2
PIO0_21-WAKEUP: D1.A J8.19 R16.2
PIO0_22: J8.15 J13.5 R153.2
RDM_RESETN: D4.C J8.13 J11.10(B5) R10.2 R110.2
RSTN_BOARDS: JP37.1 R11.2 R146.1 R147.1 R148.1
SENSOR_I2C_SCL: J13.12 J13.14(B7) U6.5 U7.8 U8.1
SENSOR_I2C_SDA: J13.8 J13.10 U6.4 U7.7 U8.6
SENSOR_INT: J13.4 R26.2 R163.2 R164.2 R165.2 U29.2
SENSOR_VDD: C14.2 C15.2 C17.2 C87.1 J13.2 R25.1 R26.1 R166.2 R229.1 U6.1(VDD) U7.1 U7.4(VDDIO) U8.5(V+) U29.5
SYS_5V0: C1.1 C4.1 C6.2 C7.1 C55.1 C83.1 L6.2 Q12.D R65.1 U1.1 U1.3 U3.1 U3.3 U4.5
USB_1V5: C2.1 J5.1 U1.5(OUT)
USB_3V0: C5.1 J4.4 U3.5(OUT)
USB_DM: J33.2 U9.35 U12.1
USB_DP: J33.3 U9.34 U12.2
VIO: C3.1 C12.1 C68.1 C71.1 C73.1 J8.3 J8.5 J11.1 J13.1 J16.1 J22.1 L7.2 Q2.G R1.1 R2.1 R5.1 R6.1 R7.1 R8.1 R13.2 R18.1 R19.2 R22.2 R23.2 R31.1 R32.1 R33.1 R34.1 R35.1 R36.1 R93.1 R98.1 R99.1 U2.1(VDD) U21.1 U21.15 U22.1 U22.10 U23.5 U24.7
VREF_MCULINK: C44.1 C45.1 R40.2 R62.2 U9.17 U10.C(CATHODE)
N56442: R89.1 U21.4
N3578794: Q10.D R93.2 U21.9
N3581084: R87.1 U21.3
N3594293: Q11.D R98.2 U22.9
N3596543: R94.1 U22.3
N3596557: R96.1 U22.4
N3596571: R95.1 U22.5
N3596575: R97.1 U22.6
N4897644: D17.C R90.2
N4898305: R90.1 U21.5
N4898918: R91.2 U21.12
N4953028: U21.6 U21.10
N12265657: C18.1 J14.7 R29.2
N12266589: C19.1 J18.7 R30.2
N12275396: J14.2 R148.2
N12275400: J14.3 R149.2
N12275404: J14.4 R150.2
N12275408: J14.5 R151.2
N12275412: J14.6 R152.2
N12276056: J15.1 R155.1
N12276068: J15.2 R156.1
N12276080: J15.3 R157.1
N12276104: J15.4 R158.1
N12276108: J15.5 R159.1
N12276112: J15.6 R160.1
N12276934: J18.2 R146.2
N12276966: J18.3 R138.2
N12276998: J18.4 R139.2
N12277030: J18.5 R140.2
N12277038: J18.6 R141.2
N12277309: J17.1 R154.1
N12277341: J17.2 R153.1
N12277373: J17.3 R135.1
N12277413: J17.4 R136.1
N12277445: J17.5 R137.1
N12277469: J17.6 R134.1
N12278499: J21.1 R128.1
N12278559: J20.2 R147.2
N12278563: J21.2 R129.1
N12278623: J20.3 R142.2
N12278627: J21.3 R130.1
N12278695: J20.4 R143.2
N12278699: J21.4 R131.1
N12278759: J20.5 R144.2
N12278763: J21.5 R132.1
N12278819: J20.6 R145.2
N12278823: J21.6 R133.1
N12278835: C20.1 J20.7 R37.2
N12295606: C16.2 U7.2
N12315434: C52.1 U11.4
N12315580: BD1.1 J33.1(VBUS) U12.6(VBUS)
N12322367: J23.3 JP37.2
N12329989: Q7.S(SOURCE) Q14.D Q27.S(SOURCE) R67.2 R75.1 R78.1 R224.2 R231.2 TP5.1(TP)
N12329993: C62.1 R75.2 R77.2 U17.3
N12330033: R76.1 U17.1 U17.4
N12330403: Q9.S(SOURCE) R83.1 TP6.1(TP) U19.5
N12330433: R78.2 U19.2
N12330505: C67.2 R82.1 R85.2 U19.7(OUTB)
N12330553: C67.1 R81.2 R85.1 U19.6
N12330797: R80.1 U19.1
N12330801: Q9.G R80.2
N12330825: Q9.D R79.2 U19.3
N12331089: Q22.D Q25.S(SOURCE) R73.1 R79.1 R224.1 TP4.1(TP)
N12331509: Q7.D Q14.S(SOURCE) R73.2
N12333663: Q7.G R72.1 R228.1
N12334532: Q8.D R228.2
N12369229: R63.2 R64.1 U9.36
N12373644: R40.1 R41.2 U9.58
N12374436: D8.A R44.2
N12374792: D9.A R45.2
N12374932: D10.A R54.2
N12375074: J31.7 R57.2
N12375164: D11.A R56.2
N12375264: D12.A R58.2
N12375326: D13.A R59.2
N12375380: D14.A R61.2
N12381948: R165.1 U8.3
N12381957: R164.1 U7.6
N12382534: R163.1 U6.8
N12393061: C41.1 C42.1 C43.1 L4.2 U9.39 U9.45
N12393117: L4.1 U9.48
N12422072: BAT3.1 BAT3.3 J5.3
N12422390: BAT2.2 BAT2.3 J4.6
N12442192: C9.1 J37.1 R6.2 R15.1 SW2.1 SW2.3
N12442224: C8.1 R5.2 R10.1 R11.1 SW1.1 SW1.3
N12449351: C10.1 R7.2 R16.1 SW3.1 SW3.3
N12450169: C11.1 R8.2 R21.1 SW4.1 SW4.3
N12453362: D1.C U2.6
N12454206: R1.2 U2.2
N12454210: R2.2 U2.3
N12480389: C53.1 J34.1(VBUS) L5.1
N12480952: D19.A L5.2
N12522256: R115.1 U28.5
N12522264: R112.2 R114.1 U28.4
N12522562: R104.2 R105.1 U25.4
N12522860: R108.2 R110.1 U27.4
N12527022: R109.1 U26.4
N12533780: R100.1 U23.4(Y)
N12537164: R92.2 U21.11
N12627127: D16.A R65.2
N12627699: D18.C(CATHODE) D19.C(CATHODE) Q12.S(SOURCE) R161.1
N12627791: C83.2 Q12.G R161.2 R162.1
N12648217: J3.2 R12.1 R17.1
N12648225: R12.2 R13.1
N12648461: R17.2 R20.2 U4.3
N12648493: R19.1 U4.1 U4.4
N12652986: J19.1 R31.2
N12653032: J19.3 R33.2
N12653078: J19.5 R32.2
N12653124: J19.7 R35.2
N12653170: J19.9 R34.2
N12653192: J19.11 R36.2
N12655772: D2.C(CATHODE) Q1.D
N12655780: D2.A R3.2
N12655848: D3.C(CATHODE) Q2.D
N12655856: D3.A R9.2
N12656530: R166.1 U6.7
N12790182: C88.1 Q20.D U30.5(OUT)
N12790214: C89.1 U30.4
N12795272: Q16.D R67.1
N12795276: Q17.D R71.1
N12795416: D20.A Q16.G R230.2
N12796249: Q20.S(SOURCE) Q22.S(SOURCE)
N12796253: Q20.G Q21.D Q22.G Q24.G Q25.G Q26.G Q27.G R66.1
N12796853: Q24.D Q25.D
N12797165: Q26.D Q27.D
N12815289: J36.4 J36.8(B4) R89.2
N12815293: J36.2 J36.6 R87.2
N12892834: C13.2 R25.2 U29.1
N12892932: R27.2 U29.4(Y)
N12893707: J13.6 R27.1 R229.2
N12901647: R71.2 R231.1

Pads without a net: J8 7 9 10 11 20; J11 7 8; J14 1; J15 7; J17 7; J18 1; J20 1; J21 7; J23 1 5 8; J24 1 2; J25 1 2 3 4; J26 4 5 6 7 8; J31 8; J33 4; J34 2 3 4; U1 4; U3 4; U6 6; U7 5; U9 6 7 11 26 40 53 68 77 80 89 93 97 98; U12 3 4 5; U23 1

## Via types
v1: diameter 0.7, hole 0.3, TOP to BOTTOM, 577 vias
v2: diameter 1, hole 0.5, TOP to BOTTOM, 136 vias

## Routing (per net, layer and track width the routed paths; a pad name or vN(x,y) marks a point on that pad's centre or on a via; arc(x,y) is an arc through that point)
1V5: length 57.5
  TOP w0.5: J1.7 33,76.18 33,87.77 J7.1 41.73,96.5 46.5,96.5 49.5,93.5 54.54,93.5 J3.3
  IN2 w0.5: J7.1 J6.2
  BOTTOM w0.5: J1.7 33.04,76.22 35.58,76.22 J2.5
1V5_SNS+: length 38.5
  TOP w0.5: 32.5,104.5 32.5,99.27 J6.1 26.25,93.02 26.25,81.47 30.25,77.47 J1.5 ; 32.5,104.5 J5.4 ; 32.5,104.5 32.5,106.5 31.96,107.04 J5.2
1V5_SNS-: length 55.6
  TOP w0.5: v1(65,103.75) 64.79,103.54 J8.1 ; J2.7 38.08,76.18 38.08,86.07 39.26,87.25 43.5,87.25 44.25,88 44.25,93.52 J7.2
  IN2 w0.5: J7.2 44.27,96.5 50.96,96.5 51.71,97.25 56.76,97.25 58.25,98.74 58.25,100.82 61.18,103.75 v1(65,103.75)
3V0: length 110.7
  TOP w0.25: R9.1 v1(85.75,119.5) ; R3.1 v1(89.75,119.5)
  TOP w0.5: v1(85.75,119.5) 85.75,118.76 85.25,118.26 85.25,118 v1(82,114.75) ; J1.3 30.25,80.01 28.23,82.03 J10.1 ; J9.1 38.51,89 36.83,87.32 J2.1
  IN2 w0.5: v1(82,114.75) 81.39,114.14 81.35,114.14 80.5,113.29 80.5,107.75 79.25,106.5 79.25,101.25 78.75,100.75 73.25,100.75 72.5,101.5 63,101.5 58,96.5 52.46,96.5 J3.1 49.24,95 48.74,95.5 45.5,95.5 44.25,94.25 44.25,88 43.75,87.5 40.25,87.5 ; 40.25,87.5 40.23,87.52 J9.1 ; 40.25,87.5 29.73,87.5 J10.1
  BOTTOM w0.5: v1(89.75,119.5) v1(85.75,119.5)
3V0_SNS+: length 34.2
  TOP w0.5: 38.5,103.25 38.5,96.73 J10.2 30.77,84.73 31.75,83.75 J1.1 ; 38.5,103.25 38.52,103.23 J4.5 ; 38.5,103.25 38.5,105.75 ; J4.3 38.52,105.77 38.5,105.75 ; 38.5,105.75 38.5,107.75 39.06,108.31 J4.1
3V0_SNS-: length 49.7
  TOP w0.5: J8.2 57.21,103.54 v1(57,103.75) ; J9.2 41.27,90.5 37.25,90.5 35.58,88.83 35.58,81.26 J2.3
  IN2 w0.35: 41.51,93.75 41.51,96.15
  IN2 w0.5: 41.51,93.75 41.51,90.26 J9.2 ; 41.51,96.15 42.61,97.25 50.5,97.25 51.25,98 56.24,98 57.25,99.01 57.25,102.72 57,102.97 v1(57,103.75)
3V3: length 60.1
  TOP w0.2: 40.81,41.22 L3.1 ; L3.1 41.5,41.94 ; L3.1 42.19,41.22 ; C38.1 39.3,43.84 ; C38.1 40.04,43 ; C38.1 39.3,42.16 ; 27.66,15.2 C51.1 ; C51.1 28.5,14.46 ; C51.1 29.34,15.2 ; U11.5 28.55,14.19 ; U11.5 28.55,12.51 ; U11.5 29.17,13.35 ; U11.5 27.93,13.35 ; 39.5,41.94 L1.1 40.19,41.22
  TOP w0.25: v1(60,76.5) C70.1 59.44,77.5 59.19,77.75 U22.16 ; U16.3 44.51,62.2 44.96,61.75 C60.1 v1(45.25,62.75) ; C23.1 v1(7,49.5) ; v1(26.5,45) 26.65,45.15 U20.B ; U24.6 54.5,67.5 54.25,67.25 C72.1 v1(53.25,66.75) ; L2.1 v1(61,16.75) ; U21.16 70.69,77.75 70.94,77.5 C69.1 v1(71.5,76.5) ; v1(76,93.5) 76,94.25 75.75,94.5 C80.1 75,95.06 74.9,95.16 U28.1 ; U26.1 62.9,95.16 63,95.06 C76.1 63.75,94.5 64,94.25 v1(64,94.01) ; R53.1 v1(10,47) ; v1(68,94.01) 68,94.25 67.75,94.5 C79.1 67,95.06 66.9,95.16 U27.1 ; R169.1 v1(57.25,42) ; U25.1 70.9,95.16 71,95.06 C75.1 71.75,94.5 72,94.25 v1(72,93.5) ; U16.5 v1(40.5,61.25) ; R61.1 v1(4.5,29) ; R55.1 v1(7,48.5) ; R56.1 v1(4.5,23) ; R54.1 v1(4.5,17) ; R88.1 v1(66,75.5) ; R59.1 v1(4.5,32) ; R101.1 52.25,69 v1(51.75,69.5) 52.25,70 R102.1 ; R45.1 v1(4.5,14) ; R44.1 v1(4.5,26) ; U18.B v1(38.65,54.35) ; R58.1 v1(4.5,20) ; R230.1 v1(16.5,54.5) ; R52.1 v1(10,45)
  BOTTOM w0.25: J31.1 2.86,48.86 3.5,49.5 v1(7,49.5)
  vias: v1(26.25,15.25) v1(27.25,15.25) v1(40.5,43.75) v1(41.5,43.75)
+3V3_1V8_ARD: length 76.5
  TOP w0.5: v1(65.75,5.75) 66.95,5.75 C21.1 67,3.82 66.9,3.72 J23.2
  IN2 w0.5: v2(51.5,57.75) 54.59,57.75 60.3,52.04 J24.8 64,47.1 64,36.71 63.65,36.36 63.65,34.14 64,33.79 64,32.71 63.65,32.36 63.65,31.64 64,31.29 64,30.71 63.65,30.36 63.65,29.64 64,29.29 64,27.46 63.65,27.11 63.65,7.85 v1(65.75,5.75)
  BOTTOM w0.5: v1(65.75,5.75) 71,5.75 71.98,4.77 J23.4 ; J22.2 v2(51.5,57.75)
GND: length 850.7
  TOP w0.2: R41.1 63.3,25.84 ; R41.1 63.3,24.16 ; R41.1 62.56,25 ; 36.96,38 C25.2 ; C25.2 38.44,38 ; C25.2 37.7,38.84 ; 24,53.88 R83.2 24,55.12 ; 50.13,110.25 R18.2 51.37,110.25 ; 84.72,91.14 J21.8 84.72,88.86 ; 60.09,17.7 C37.2 58.41,17.7 ; 48.12,116.25 R24.1 46.88,116.25 ; Q1.S 92.27,117.27 ; Q1.S 93.16,116.48 ; Q1.S 91.38,116.48 ; J11.9 46.17,123.1 ; J11.9 44.75,123.1 ; J11.9 44.75,121.68 ; 1.36,84.55 SW1.4 2.2,85.34 ; v1(42.75,67) 42.73,67.02 Q8.S ; 28.23,100.82 J5.5 ; J5.5 27.09,101.96 ; J5.5 28.23,103.1 ; J5.5 29.37,101.96 ; C19.2 88.34,78.45 ; C19.2 87.5,79.19 ; C19.2 86.66,78.45 ; D4.A 43,116.64 ; D4.A 43.64,116.05 ; D4.A 42.36,116.05 ; 35.55,55.69 U18.C 35.55,54.31 ; J28.2 16.37,35 ; J28.2 15.23,33.86 ; J28.2 15.23,36.14 ; J28.2 14.09,35 ; 87.5,38.71 C18.2 ; C18.2 87.5,40.19 ; C18.2 86.66,39.45 ; C18.2 88.34,39.45 ; 14.09,23 J30.2 ; J30.2 15.23,21.86 ; J30.2 15.23,24.14 ; J30.2 16.37,23 ; J23.7 79.6,3.68 ; J23.7 78.46,2.54 ; J23.7 79.6,1.4 ; J23.7 80.74,2.54 ; 1.36,76.55 SW2.4 2.2,77.34 ; 38.2,1.33 J33.F6 37.18,2.62 ; 11.5,56.13 J32.2 ; J32.2 12.64,57.27 ; J32.2 10.36,57.27 ; J32.2 11.5,58.41 ; 37.7,42.16 C38.2 37.7,43.84 ; 66.2,78.71 U21.8 65.41,78.25 ; 39.38,17.5 C47.2 40.62,17.5 ; 1.36,80.45 SW1.2 2.2,79.66 ; C90.1 v1(14.5,79) ; C90.1 15.7,79.84 ; C90.1 15.7,78.16 ; 32.61,30.02 U10.NC ; U10.NC 33.5,30.81 ; U10.NC 33.5,29.23 ; 68.04,57.75 U29.3 67.4,58.39 ; 15.23,27.86 J29.2 ; J29.2 14.09,29 ; J29.2 15.23,30.14 ; J29.2 16.37,29 ; 17.52,58.13 Q16.S 17.52,59.91 ; 48.55,29 v1(50.5,29) 52.45,29 ; 42.77,99.55 J4.8 ; J4.8 42.77,101.83 ; J4.8 43.91,100.69 ; J4.8 41.63,100.69 ; 38.41,62.3 C61.2 ; C61.2 40.09,62.3 ; C61.2 39.25,61.56 ; J35.2 24.5,46.91 ; J35.2 24.5,44.63 ; J35.2 25.64,45.77 ; J35.2 23.36,45.77 ; C88.2 17.3,73.84 ; C88.2 17.3,72.16 ; C88.2 16.56,73 ; 32.66,25.8 R43.2 ; R43.2 34.34,25.8 ; R43.2 33.5,25.06 ; 31.62,57.5 C65.2 30.38,57.5 ; 2.15,43.17 J31.9 ; J31.9 2.15,41.75 ; J31.9 3.57,41.75 ; 12.5,76.38 C89.2 ; C89.2 12.5,77.62 ; C89.2 v1(11.5,77) ; 29.45,45.19 U20.C 29.45,43.81 ; 1.36,68.55 SW3.4 2.2,69.34 ; 83.58,21 J15.8 ; J15.8 84.72,19.86 ; J15.8 85.86,21 ; J15.8 84.72,22.14 ; R14.2 92.39,115 ; R14.2 91.75,115.62 ; R14.2 91.75,114.38 ; v1(64.75,71.25) 64.75,71 64.65,70.9 ; J20.8 85.86,112.86 ; J20.8 84.72,114 ; J20.8 84.72,111.72 ; J20.8 83.58,112.86 ; J17.8 85.86,60 ; J17.8 84.72,58.86 ; J17.8 84.72,61.14 ; 1.36,60.55 SW4.4 2.2,61.34 ; 24,51.62 R81.1 24,50.38 ; 86.66,108.45 C20.2 ; C20.2 87.5,109.19 ; C20.2 87.5,107.71 ; C20.2 88.34,108.45 ; 29.63,101.96 J5.6 ; J5.6 30.77,103.1 ; J5.6 30.77,100.82 ; 55.89,69.5 v1(54.75,69.5) 53.61,69.5 ; 60.38,93.5 C77.2 61.62,93.5 ; 29.89,4.45 J33.F1 ; J33.F1 30.78,3.58 ; J33.F1 30.78,5.32 ; 68.75,64.86 C16.1 68.13,65.5 ; 45.36,116.05 D5.A ; D5.A 46.64,116.05 ; D5.A 46,116.64 ; Q17.S 17.52,65.91 ; Q17.S 16.73,65.02 ; Q17.S 17.52,64.13 ; 15.66,122.6 R2.3 17.34,122.6 ; 67.25,64.86 C15.1 67.87,65.5 ; 62.56,36 C24.2 ; C24.2 63.3,35.16 ; C24.2 63.3,36.84 ; 29.5,114.66 v2(29.5,119.5) 29.5,124.34 ; J23.6 77.06,3.68 ; J23.6 77.06,1.4 ; J23.6 78.2,2.54 ; J23.6 75.92,2.54 ; 9.36,116.1 BAT2.1 ; BAT2.1 10.5,117.24 ; BAT2.1 11.64,116.1 ; BAT2.1 10.5,114.96 ; J34.F2 17.23,5.32 ; J34.F2 18.12,4.45 ; J34.F2 17.23,3.58 ; J34.F4 13.85,3 14,3 ; 9.8,1.33 J34.F3 10.82,2.62 ; C21.2 67.84,7.3 ; C21.2 66.16,7.3 ; C21.2 67,6.56 ; C21.2 67,8.04 ; J14.8 84.72,45 ; J14.8 85.86,43.86 ; J14.8 83.58,43.86 ; J14.8 84.72,42.72 ; 47.29,123.1 J11.5 48.71,123.1 ; D16.C 3.82,13.24 ; D16.C 3.08,12.5 ; D16.C 3.82,11.76 ; J33.F5 34.15,3 34,3 ; J33.F4 31.85,3 32,3 ; 54.5,20.2 U9.46 54.5,22.34 ; 40.23,99.55 J4.7 ; J4.7 41.37,100.69 ; J4.7 40.23,101.83 ; 75.3,72.16 C87.2 ; C87.2 75.3,73.84 ; C87.2 74.56,73 ; 15.34,122.6 R1.3 13.66,122.6 ; 34.38,25.5 C22.2 35.62,25.5 ; 17.3,42.34 C54.2 17.3,40.66 ; 26.98,59.1 U19.4 27.52,58.26 ; 40.73,71.02 Q21.S ; Q21.S 41.52,71.91 ; Q21.S v1(42.73,71.02) ; 46,111.38 C4.2 46,112.62 ; 35.23,3.58 J33.F2 ; J33.F2 35.23,5.32 ; J33.F2 36.12,4.45 ; 1.36,56.45 SW4.2 2.2,55.66 ; 47.12,41 C30.2 45.88,41 ; 29.34,6.95 C50.1 27.66,6.95 ; 41.85,18.79 Y1.4 41.85,17.05 ; 17.3,40.34 C55.2 17.3,38.66 ; 44.15,16.95 Y1.2 44.15,15.21 ; 55.5,40.06 R168.1 56.34,40.8 ; 65,67 64.65,67.35 U6.9 ; 70,55.37 C13.1 70,54.13 ; 33.63,27.98 U10.A ; U10.A 34.52,28.77 ; U10.A 34.52,27.19 ; U30.2 v1(16.5,76) ; U6.2 64.65,70.9 ; 64.65,70.9 64.25,70.5 U6.3 ; 74.65,69.41 U8.4 75.14,69.98 ; 31.66,57.8 C64.2 ; C64.2 33.34,57.8 ; C64.2 32.5,57.06 ; U6.10 65.05,67.46 65.25,67.26 ; 28.82,2.62 J33.F3 27.8,1.33 ; 2.2,71.66 SW2.2 1.36,72.45 ; 36,57.62 C63.2 35.36,57 ; 27.37,111.5 C2.2 26.75,112.14 ; 31.12,16.5 C52.2 30.5,17.14 ; 9.36,75.77 J37.2 ; J37.2 10.5,76.91 ; J37.2 11.64,75.77 ; J37.2 10.5,74.63 ; 12.78,3.58 J34.F1 11.89,4.45 ; D7.A 52.64,116.05 ; D7.A 52,116.64 ; D7.A 51.36,116.05 ; J34.F5 16.15,3 16,3 ; 20.2,1.33 J34.F6 19.18,2.62 ; 2.2,63.66 SW3.2 1.36,64.45 ; 62.84,51.94 J24.7 62.84,49.66 ; 34,111.62 C1.2 34,110.38 ; 54.8,19.59 C43.2 54.8,17.91 ; R20.1 48.87,99.25 ; R20.1 48.25,98.61 ; R20.1 47.63,99.25 ; 34.38,21.5 R39.2 35,20.86 ; 52.88,116.25 C12.2 54.12,116.25 ; 48.36,116.05 D6.A ; D6.A 49.64,116.05 ; D6.A 49,116.64 ; Q2.S 89.16,116.48 ; Q2.S 88.27,117.27 ; Q2.S 87.38,116.48
  TOP w0.25: 55,15.75 C49.2 C48.2 55,17.94 55.05,17.99 ; v1(35.5,61.5) 36,61.5 36.5,62 U17.2 ; U22.15 57.75,76 58,75.75 58.5,75.75 v1(58.75,76) ; D7.A v1(52,115) ; C14.1 66,67.5 65.5,67 65.25,67 ; U18.C v1(34.5,55) ; R1.3 14.5,123.75 ; R115.2 v1(74,92.5) ; U10.NC 34.52,30.02 35,30.5 ; C32.2 37.25,24 37,23.75 v1(37,23) C27.2 ; C34.2 51.5,41.75 ; v1(76,96.75) 75.75,96.75 75.5,96.5 U28.2 ; C55.2 v1(18.5,39.5) ; v1(34.75,26.5) 35,26.25 C22.2 ; v1(34.5,5.5) 34.3,5.3 J33.5 34.3,4.12 ; U21.8 67.75,78.25 v1(68,78) ; U9.99 45,38.5 v1(45.5,39) ; C2.2 v1(25.75,111.5) ; 55.25,65 54.5,65 54.25,65.25 C72.2 ; 55.25,65 v1(56.25,65) ; 55.25,65 C73.2 ; U19.4 27.52,59.98 v1(27.25,60.25) ; SW4.2 v1(2.2,58.5) SW4.4 ; C54.2 v1(18.5,41.5) ; C75.2 71,92.75 70.75,92.5 70,92.5 ; Q16.S 16.73,59.02 16.5,58.79 v1(16.5,58) ; v1(61,75.25) 61,74.75 61.27,74.48 Q10.S ; R77.1 v1(31,62.5) ; U9.52 v1(55.75,23.5) ; R111.2 v1(66,92.5) ; 94.5,123.32 93.91,123.32 ; R41.1 v1(64.5,25) ; U3.2 v1(41.5,112) ; 65.25,67 v1(65.25,66.5) ; 65.25,67 65.25,67.26 ; 65.25,67 65,67 ; C53.2 v1(16.5,6) 16.5,5.39 16.3,5.19 J34.5 16.3,4.12 ; R24.1 v1(47.5,115) ; v1(51.75,27.75) v1(50.5,29) ; v1(50.5,29) v1(49.25,30.25) ; v1(50.5,29) v1(50.5,30.25) ; v1(50.5,29) v1(50.5,27.75) ; v1(50.5,29) v1(51.75,30.25) ; C4.2 v1(47,112) ; R51.2 v1(37,33) ; Q1.S 92.27,115.73 92.56,115.44 92.56,115.19 v1(93,114.75) 92.75,114.75 92.5,115 ; C41.2 C42.2 v1(51,18.25) ; SW3.4 v1(2.2,66.5) SW3.2 ; U9.47 55,22.5 54.75,22.75 v1(54.5,22.75) 54.75,22.5 ; U16.2 44.46,61.25 44.71,61 44.71,60.29 v1(45.25,59.75) C60.2 ; C64.2 v1(32.5,59) ; SW2.2 v1(2.2,74.5) SW2.4 ; C29.2 v1(64.5,30) ; C11.2 v1(5.5,61) ; C50.1 v1(28.5,5.75) ; C1.2 v1(35,111) ; J8.14 57.41,111.16 57,110.75 v1(57,110) 57.1,109.9 J8.12 ; U21.2 69.25,80 69.5,80.25 70,80.25 v1(70.25,80) ; v1(54.25,80) 54.5,80.25 55,80.25 55.25,80 U22.7 ; C15.1 v1(66.25,65.5) ; U9.18 41.5,26.5 v1(41.25,26.25) 41.5,26 U9.19 ; Q11.S 53.77,74.52 53.5,74.25 v1(53.5,73.5) ; U8.2 v1(74,67) ; Y1.2 45.04,16.08 45.46,16.5 C46.2 v1(46,15.5) ; v1(44,64) 43.75,64.25 R74.2 ; v1(5,85) 5.5,84.5 C8.2 ; J8.8 57.14,107.36 v1(57,107.5) ; v1(64,96.75) 63.75,96.5 U26.2 ; 70,92.5 R106.2 ; 70,92.5 v1(69,92.5) C74.2 ; R81.1 v1(23,51) ; C3.2 v1(10.5,119.5) ; v1(50.75,111.25) R18.2 ; C87.2 v1(76.5,73) ; C16.1 v1(70,65.5) ; v1(27.25,16.5) 27.55,16.8 C51.2 29.45,16.8 29.75,16.5 C52.2 ; R83.2 v1(23,54.5) ; R64.2 v1(49,15.5) ; C45.2 37.5,26 v1(37,26.5) 37.5,27 C44.2 ; R60.2 v1(10,46) ; C78.2 v1(65,92.5) ; v1(70,66.5) 69.88,66.62 U7.3 ; U24.2 55,69.75 v1(54.75,69.5) ; Q2.S v1(88.27,114.75) ; R47.2 v1(50.5,42) ; U1.2 v1(29.5,111) ; C71.2 v1(61,79.5) ; D5.A v1(46,115) ; C76.2 v1(63,92.5) ; Y1.4 40.58,17.92 v1(40,18.5) C47.2 ; R2.3 16.5,123.75 ; C24.2 v1(64.5,36) ; C38.2 v1(36.5,43) ; J8.4 57.18,104.82 v1(57,105) ; v1(50,22.75) U9.37 ; v1(71,55) 70.75,54.75 C13.1 ; 47.5,97.5 46.5,97.5 ; U11.2 v1(29.5,12) ; D6.A v1(49,115) ; 95.75,116.5 95,116.5 ; v1(36.25,5.5) 36.1,5.35 36.1,4 ; U2.5 10.5,121 10.25,121.25 10.25,122.5 10.5,122.75 v1(11.35,122.75) U2.4 ; J12.6 70.17,106.08 v1(70,106.25) ; C39.2 v1(37,28) 37,28.75 37.25,29 C40.2 ; R39.2 v1(36,21.5) ; C77.2 v1(61,92.5) ; C31.2 v1(37,30.5) 37,31.25 37.25,31.5 C26.2 ; R162.2 v1(11.5,15.5) ; U22.8 54,78.25 v1(53.5,78.75) ; C66.2 v1(30,46.5) ; C5.2 v1(39,113.5) ; J12.7 77.53,107.36 77.64,107.25 v1(78.25,107.25) ; v1(76,75.75) 75.95,75.8 U23.3 ; U10.A v1(36,27.98) ; J8.6 57.17,106.08 v1(57,106.25) ; SW1.4 v1(2.2,82.5) SW1.2 ; U21.7 66.75,80 66.5,80.25 66,80.25 v1(65.75,80) ; R227.1 v1(43.75,68) ; C7.2 v1(54.25,107.25) ; C62.2 v1(31,61.5) ; C30.2 v1(46.5,42.5) ; v1(35.25,56) 35.75,56 36,56.25 C63.2 ; D16.C v1(5,12.5) ; C28.2 v1(50,15.5) ; C80.2 v1(75,92.5) ; C68.2 v1(72.5,79.5) ; U20.C v1(30.5,44.5) ; D4.A v1(43,115) ; C10.2 v1(5.5,69) ; C69.2 v1(72.5,76.5) ; C36.2 v1(57.75,17) ; v1(76.5,71.5) C17.1 75,71.21 74.65,70.86 U8.4 ; C81.2 v1(73,92.5) ; v1(48,22.75) U9.33 ; R43.2 v1(33.5,27) ; C6.1 v1(52.25,109.5) ; C37.2 v1(59.25,16.75) ; R48.2 v1(64.5,34.5) ; v1(87.5,77.25) C19.2 ; R49.2 37.5,35 v1(37,35.5) 37.7,36.2 C25.2 ; C9.2 v1(5.5,77) ; U27.2 67.29,96.5 67.54,96.75 v1(68,96.75) ; C35.2 56.75,17 ; v1(58.75,80) 58.5,80.25 58,80.25 57.75,80 U22.2 ; C12.2 v1(53.5,115) ; R84.1 v1(30,47.5) ; R50.2 v1(47,15.5) ; Q17.S v1(18.73,65.02) ; C88.2 v1(18.5,73) ; v1(34.5,7.5) 34.2,7.8 U12.7 ; R168.1 v1(55.5,42) ; U25.2 71.54,96.5 71.79,96.75 v1(72,96.75) ; C79.2 v1(67,92.5) ; J11.3 49.27,123.23 ; 90.5,123.32 89.86,123.32 ; C70.2 v1(61,76.5) ; v1(48.25,103.25) U4.2 ; C33.2 v1(64.5,32) ; R46.2 v1(64.5,23.25) ; C23.2 v1(9,50.5) ; C65.2 v1(31,58.5)
  IN1 w0.2: 79.6,1.35 J23.7 ; J23.7 80.79,2.54 ; J23.7 78.41,2.54 ; J23.7 79.6,3.73 ; J17.8 85.91,60 ; J17.8 84.72,61.19 ; J17.8 84.72,58.81 ; J17.8 83.53,60 ; J30.2 15.23,24.19 ; J30.2 15.23,21.81 ; J30.2 14.04,23 ; J30.2 16.42,23 ; 12.78,3.58 J34.F1 ; J34.F1 11.86,4.45 ; J34.F1 13.7,4.45 ; J34.F1 12.78,5.32 ; J33.F1 31.7,4.45 ; J33.F1 30.78,5.32 ; J33.F1 30.78,3.58 ; J33.F1 29.86,4.45 ; 47.29,123.1 J11.5 48.71,123.1 ; 75.87,2.54 J23.6 ; J23.6 77.06,3.73 ; J23.6 77.06,1.35 ; J23.6 78.25,2.54 ; J37.2 10.5,76.96 ; J37.2 11.69,75.77 ; J37.2 9.31,75.77 ; J37.2 10.5,74.58 ; J4.7 41.42,100.69 ; J4.7 39.04,100.69 ; J4.7 40.23,101.88 ; J4.7 40.23,99.5 ; J34.F6 19.18,2.62 ; J34.F6 20.2,1.33 ; J34.F6 17.26,1.33 ; 34.31,4.45 J33.F2 ; J33.F2 35.23,5.32 ; J33.F2 36.15,4.45 ; J33.F2 35.23,3.58 ; 14.04,29 J29.2 ; J29.2 16.42,29 ; J29.2 15.23,27.81 ; J29.2 15.23,30.19 ; J5.6 30.77,103.15 ; J5.6 30.77,100.77 ; J5.6 29.58,101.96 ; J5.6 31.96,101.96 ; 84.72,111.67 J20.8 ; J20.8 83.53,112.86 ; J20.8 85.91,112.86 ; J20.8 84.72,114.05 ; J34.F3 12.74,1.33 ; J34.F3 10.82,2.62 ; J34.F3 9.8,1.33 ; 2.15,43.17 J31.9 ; J31.9 2.15,41.75 ; J31.9 3.57,41.75 ; 83.53,43.86 J14.8 ; J14.8 85.91,43.86 ; J14.8 84.72,45.05 ; J14.8 84.72,42.67 ; J21.8 84.72,91.19 ; J21.8 83.53,90 ; J21.8 84.72,88.81 ; J21.8 85.91,90 ; 27.04,101.96 J5.5 ; J5.5 28.23,100.77 ; J5.5 28.23,103.15 ; J5.5 29.42,101.96 ; 35.26,1.33 J33.F6 ; J33.F6 37.18,2.62 ; J33.F6 38.2,1.33 ; J32.2 12.69,57.27 ; J32.2 11.5,58.46 ; J32.2 10.31,57.27 ; J32.2 11.5,56.08 ; 61.65,50.8 J24.7 ; J24.7 62.84,51.99 ; J24.7 62.84,49.61 ; J24.7 64.03,50.8 ; 15.23,33.81 J28.2 ; J28.2 15.23,36.19 ; J28.2 16.42,35 ; J28.2 14.04,35 ; J34.F2 17.23,5.32 ; J34.F2 18.15,4.45 ; J34.F2 16.31,4.45 ; J34.F2 17.23,3.58 ; 42.77,99.5 J4.8 ; J4.8 41.58,100.69 ; J4.8 43.96,100.69 ; J4.8 42.77,101.88 ; 23.31,45.77 J35.2 ; J35.2 25.69,45.77 ; J35.2 24.5,46.96 ; J35.2 24.5,44.58 ; 10.5,114.91 BAT2.1 ; BAT2.1 11.69,116.1 ; BAT2.1 10.5,117.29 ; BAT2.1 9.31,116.1 ; J33.F3 30.74,1.33 ; J33.F3 27.8,1.33 ; J33.F3 28.82,2.62 ; 83.53,82.86 J18.8 ; J18.8 84.72,81.67 ; J18.8 84.72,84.05 ; J18.8 85.91,82.86 ; 44.75,121.68 J11.9 ; J11.9 44.75,123.1 ; J11.9 46.17,123.1 ; 83.53,21 J15.8 ; J15.8 84.72,19.81 ; J15.8 85.91,21 ; J15.8 84.72,22.19 ; 2.15,45.71 J31.5 2.15,44.29
  IN1 w0.25: 28.5,119.5 v2(29.5,119.5) 30.5,119.5 ; 2.02,46.27 J31.3 J31.5 ; J11.3 49.27,123.23
  IN2 w0.2: J34.F2 18.15,4.45 ; J34.F2 16.31,4.45 ; J34.F2 17.23,5.32 ; J34.F2 17.23,3.58 ; 77.06,1.35 J23.6 ; J23.6 78.25,2.54 ; J23.6 75.87,2.54 ; J23.6 77.06,3.73 ; 61.65,50.8 J24.7 ; J24.7 62.84,51.99 ; J24.7 62.84,49.61 ; J24.7 64.03,50.8 ; 84.72,19.81 J15.8 ; J15.8 85.91,21 ; J15.8 83.53,21 ; J15.8 84.72,22.19 ; 84.72,42.67 J14.8 ; J14.8 84.72,45.05 ; J14.8 85.91,43.86 ; J14.8 83.53,43.86 ; 85.91,60 J17.8 84.72,58.81 ; J18.8 85.91,82.86 ; J18.8 84.72,84.05 ; J18.8 84.72,81.67 ; J33.F2 35.23,5.32 ; J33.F2 36.15,4.45 ; J33.F2 34.31,4.45 ; J33.F2 35.23,3.58 ; 12.78,3.58 J34.F1 ; J34.F1 11.86,4.45 ; J34.F1 12.78,5.32 ; J34.F1 13.7,4.45 ; J33.F6 37.18,2.62 ; J33.F6 38.2,1.33 ; J33.F6 35.26,1.33 ; J23.7 80.79,2.54 ; J23.7 79.6,1.35 ; J23.7 78.41,2.54 ; J23.7 79.6,3.73 ; 44.75,123.1 J11.9 ; J11.9 44.75,121.68 ; J11.9 46.17,123.1 ; 9.31,116.1 BAT2.1 ; BAT2.1 10.5,117.29 ; BAT2.1 11.69,116.1 ; BAT2.1 10.5,114.91 ; 2.15,41.75 J31.9 ; J31.9 2.15,43.17 ; J31.9 3.57,41.75 ; J33.F1 31.7,4.45 ; J33.F1 29.86,4.45 ; J33.F1 30.78,3.58 ; J33.F1 30.78,5.32 ; J34.F6 19.18,2.62 ; J34.F6 17.26,1.33 ; J34.F6 20.2,1.33 ; J34.F3 10.82,2.62 ; J34.F3 9.8,1.33 ; J34.F3 12.74,1.33 ; J21.8 85.91,90 ; J21.8 84.72,91.19 ; J21.8 84.72,88.81 ; 2.15,45.71 J31.5 2.15,44.29 ; 47.29,123.1 J11.5 48.71,123.1 ; J33.F3 28.82,2.62 ; J33.F3 30.74,1.33 ; J33.F3 27.8,1.33
  BOTTOM w0.2: J37.2 10.5,76.91 ; J37.2 10.5,74.63 ; J37.2 9.36,75.77 ; J37.2 11.64,75.77 ; J23.7 79.6,3.68 ; J23.7 79.6,1.4 ; J23.7 78.46,2.54 ; J23.7 80.74,2.54 ; 84.72,81.72 J18.8 ; J18.8 85.86,82.86 ; J18.8 84.72,84 ; J18.8 83.58,82.86 ; J34.F6 20.2,1.33 ; J34.F6 19.18,2.62 ; J34.F6 17.26,1.33 ; 84.72,19.86 J15.8 ; J15.8 83.58,21 ; J15.8 84.72,22.14 ; J15.8 85.86,21 ; J30.2 15.23,24.14 ; J30.2 15.23,21.86 ; J30.2 14.09,23 ; J30.2 16.37,23 ; 30.78,3.58 J33.F1 ; J33.F1 29.86,4.45 ; J33.F1 30.78,5.32 ; J33.F1 31.7,4.45 ; J28.2 15.23,36.14 ; J28.2 16.37,35 ; J28.2 14.09,35 ; J21.8 84.72,91.14 ; J21.8 84.72,88.86 ; J21.8 85.86,90 ; J21.8 83.58,90 ; J17.8 85.86,60 ; J17.8 84.72,61.14 ; J17.8 83.58,60 ; J17.8 84.72,58.86 ; J24.7 63.98,50.8 ; J24.7 62.84,49.66 ; J24.7 61.7,50.8 ; 9.36,116.1 BAT2.1 ; BAT2.1 10.5,117.24 ; BAT2.1 11.64,116.1 ; BAT2.1 10.5,114.96 ; J23.6 78.2,2.54 ; J23.6 77.06,1.4 ; J23.6 75.92,2.54 ; J23.6 77.06,3.68 ; 83.58,43.86 J14.8 ; J14.8 85.86,43.86 ; J14.8 84.72,42.72 ; J35.2 25.64,45.77 ; J35.2 23.36,45.77 ; J35.2 24.5,44.63 ; J35.2 24.5,46.91 ; 17.23,3.58 J34.F2 ; J34.F2 16.31,4.45 ; J34.F2 18.15,4.45 ; J34.F2 17.23,5.32 ; J34.F1 12.78,5.32 ; J34.F1 13.7,4.45 ; J34.F1 11.86,4.45 ; J34.F1 12.78,3.58 ; 14.09,29 J29.2 ; J29.2 15.23,30.14 ; J29.2 16.37,29 ; J33.F2 35.23,5.32 ; J33.F2 34.31,4.45 ; J33.F2 36.15,4.45 ; 83.58,112.86 J20.8 ; J20.8 85.86,112.86 ; J20.8 84.72,111.72 ; J20.8 84.72,114 ; J32.2 11.5,58.41 ; J32.2 10.36,57.27 ; J32.2 12.64,57.27 ; J32.2 11.5,56.13 ; J34.F3 10.82,2.62 ; J34.F3 9.8,1.33 ; J34.F3 12.74,1.33 ; 44.75,121.68 J11.9 ; J11.9 44.75,123.1 ; J11.9 46.17,123.1 ; J33.F3 28.82,2.62 ; J33.F3 27.8,1.33 ; J33.F3 30.74,1.33 ; 38.2,1.33 J33.F6 35.26,1.33 ; 2.15,44.29 J31.5 2.15,45.71 ; 47.29,123.1 J11.5 48.71,123.1 ; 2.15,41.75 J31.9 ; J31.9 2.15,43.17 ; J31.9 3.57,41.75
  BOTTOM w0.25: v1(51.75,30.25) v1(51.75,29) ; v1(50.5,29) v1(51.75,27.75)
  vias: v1(13,123.75) v1(15,123.75) v1(38,5.5) v1(40.5,62.5) v1(40.75,3) v1(43,5.5) v1(44.25,10.25) v1(48.25,10.25) v1(49.25,29) v1(49.25,27.75) v1(52.5,40.5) v1(54.75,20) v1(56.5,78) v1(63.25,58) v1(68.5,57.75) v1(87.5,38.25) v2(1,114) v2(1,109) v2(1,104) v2(1,99) v2(1,94) v2(1,89) v2(1,83.25) v2(1,79) v2(1,74) v2(1,69.5) v2(1,65.5) v2(1,61.75) v2(1,55) v2(1,51) v2(1,41) v2(1,36) v2(1,31.5) v2(1,26) v2(1,21) v2(1,16.75) v2(1,11) v2(8,11) v2(9,104) v2(9,94) v2(9,53) v2(10,79) v2(10,70) v2(10,62) v2(11,124) v2(13,99) v2(14,25) v2(15,112) v2(16.5,124) v2(20.75,1) v2(21,124) v2(21,6) v2(22,15) v2(24,25) v2(25.75,1) v2(26,6) v2(27.82,74.62) v2(30,92) v2(33,12) v2(34,48) v2(35,97) v2(36,124) v2(36,106) v2(39,15) v2(40,57) v2(40.75,45.5) v2(40.75,1) v2(41,124) v2(45.75,1) v2(46,124) v2(46,106) v2(46,100) v2(50.75,1) v2(51,124) v2(51,81) v2(54,124) v2(54,7) v2(54,1) v2(56,119) v2(59,124) v2(59,7) v2(59,1) v2(60.5,39) v2(64,124) v2(64,119) v2(68,12) v2(69,124) v2(69,21) v2(69,1) v2(74,124) v2(74,119) v2(74,41) v2(74,31) v2(74,24) v2(74,17) v2(74,7) v2(74,1) v2(79,124) v2(79,7) v2(79,1) v2(84,124) v2(84,119) v2(84,12) v2(84,1) v2(85,88) v2(86,71) v2(86,56) v2(88.25,124) v2(89,31) v2(89,17) v2(89,7) v2(89,1) v2(91,104) v2(91,99.25) v2(92,87) v2(92,56) v2(92.75,72.5) v2(94,12) v2(94,1) v2(95.75,124) v2(97,69) v2(98,87) v2(98,56) v2(98,31) v2(99,99) v2(99,17) v2(99,1) v2(104,114.5) v2(104,109) v2(104,104) v2(104,99) v2(104,94) v2(104,88.25) v2(104,79) v2(104,74) v2(104,69) v2(104,65) v2(104,61.5) v2(104,56) v2(104,51) v2(104,46) v2(104,41) v2(104,36) v2(104,31) v2(104,27.13) v2(104,22.75) v2(104,17) v2(104,12) v2(104,1)
